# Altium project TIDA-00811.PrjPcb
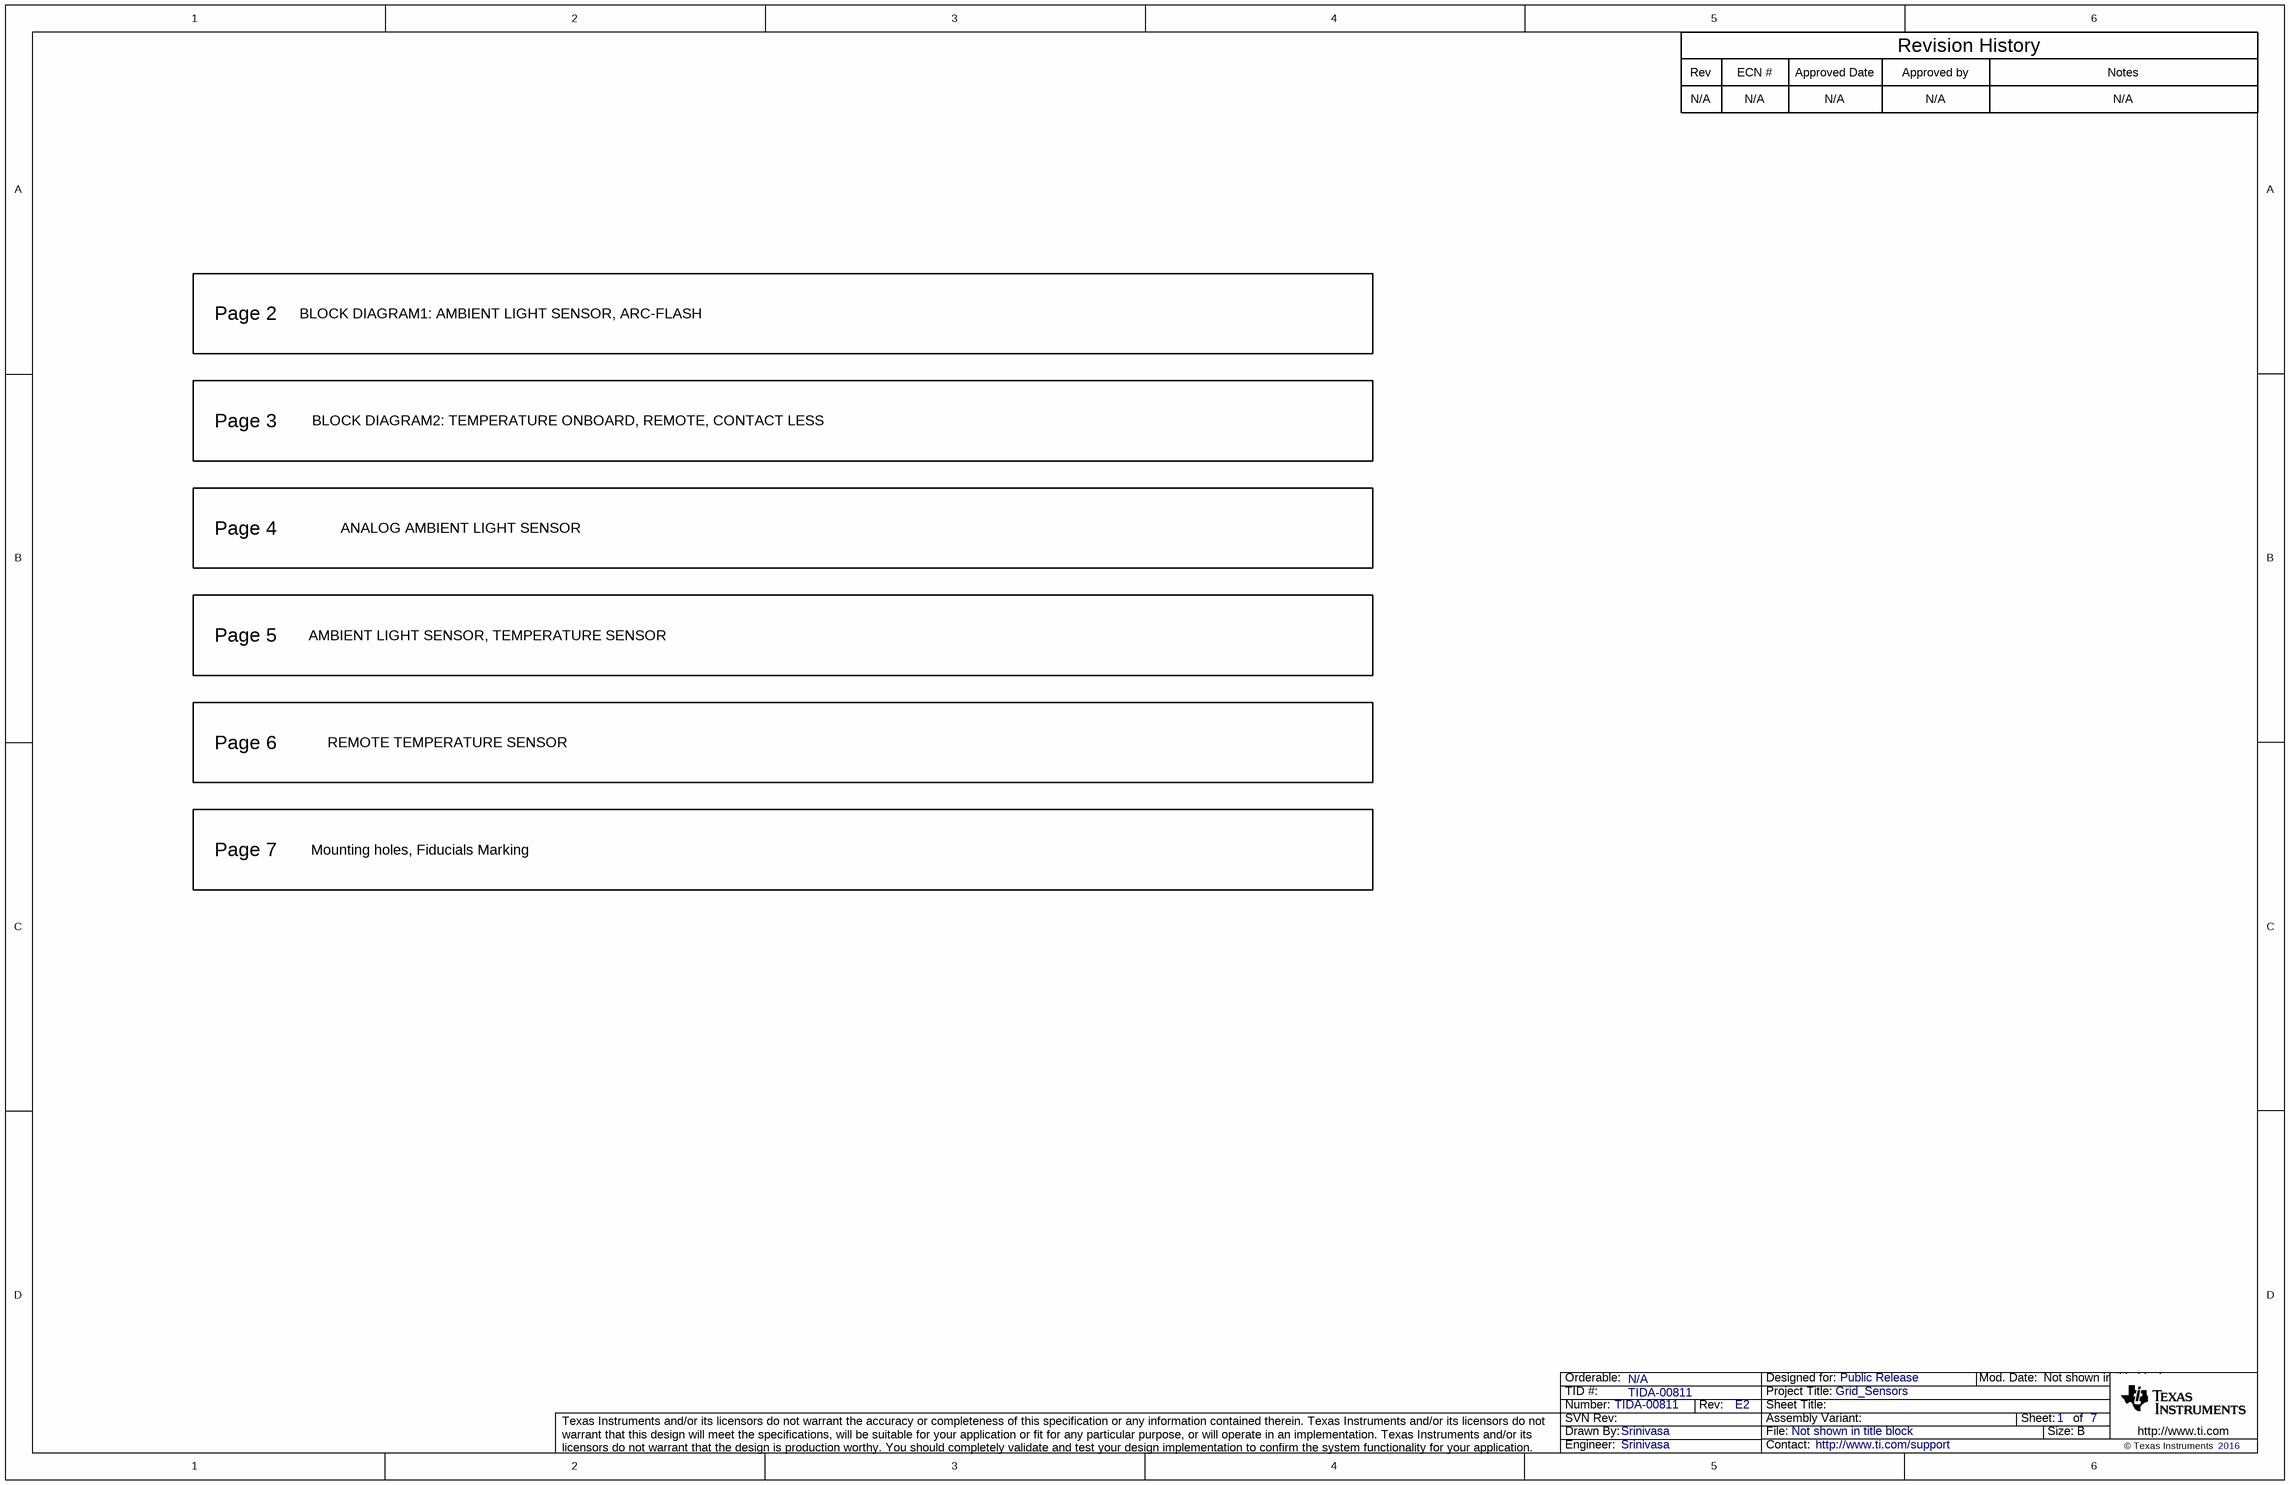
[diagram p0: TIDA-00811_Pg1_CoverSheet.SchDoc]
EVM_orderable: N/A; TID: TIDA-00811; TechSupport: http://www.ti.com/support; SCH_Rev: E2; PRJ_Title: Grid_Sensors; PRJ_Number: TIDA-00811; PRJ_Engineer: Srinivasa; PRJ_Customer: Public Release; PCB_Rev: E2; PCB_Layout: Manjunath M; CopyrightYear: 2016
7 sheets, 222 parts. Net scope: flat (ports and power ports of the same name join across sheets).
Board file: TIDA-00811_PCB.PcbDoc
Sheets:
  TIDA-00811_Pg1_CoverSheet.SchDoc
  TIDA-00811_Pg2_Block Diagram1.SchDoc
  TIDA-00811_Pg3_Block Diagram2.SchDoc
  TIDA-00811_Pg4.SchDoc
  TIDA-00811_Pg5.SchDoc
  TIDA-00811_Pg6.SchDoc
  TIDA-00811_Pg7_EVM_Hardware.SchDoc

## Sheet TIDA-00811_Pg1_CoverSheet.SchDoc
size 431 x 279 mm; Date: Not shown in title block; ApprovedBy: Not shown in title block; CheckedBy: Not shown in title block; Author: Not shown in title block; CompanyName: Not shown in title block; DrawnBy: Srinivasa; Engineer: Not shown in title block; Organization: Not shown in title block; Address1: Not shown in title block; Address2: Not shown in title block; Address3: Not shown in title block; Address4: Not shown in title block; DocumentNumber: 1; Revision: Use project parameter SCH_Rev; SheetNumber: 1; SheetTotal: 7; PageSetup: Record=PageOptions¦CenterHorizontal=True¦CenterVertical=True¦PrintScale=1.00¦XCorrection=1.00¦YCorrection=1.00¦PrintKind=0¦BorderSize=5000000¦LeftOffset=0¦BottomOffset=0¦Orientation=2¦PaperLength=1000¦PaperWidth=1000¦Scale=100¦PaperSource=15¦PrintQuality=600¦MediaType=1¦DitherType=10¦PaperKind=Letter¦PrintScaleMode=1

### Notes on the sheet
- Rev
- N/A
- ECN #
- Approved Date
- Approved by
- Revision History
- Notes
- Page 2
- BLOCK DIAGRAM1: AMBIENT LIGHT SENSOR, ARC-FLASH
- Page 3
- BLOCK DIAGRAM2: TEMPERATURE ONBOARD, REMOTE, CONTACT LESS
- Page 4
- ANALOG AMBIENT LIGHT SENSOR
- Page 5
- AMBIENT LIGHT SENSOR, TEMPERATURE SENSOR
- Page 6
- REMOTE TEMPERATURE SENSOR
- Page 7
- Mounting holes, Fiducials Marking

## Sheet TIDA-00811_Pg2_Block Diagram1.SchDoc
size 431 x 279 mm; Date: Not shown in title block; ApprovedBy: Not shown in title block; CheckedBy: Not shown in title block; Author: Not shown in title block; CompanyName: Not shown in title block; DrawnBy: Srinivasa; Engineer: Not shown in title block; Organization: Not shown in title block; Address1: Not shown in title block; Address2: Not shown in title block; Address3: Not shown in title block; Address4: Not shown in title block; DocumentNumber: 1; Revision: Use project parameter SCH_Rev; SheetNumber: 2; SheetTotal: 7; PageSetup: Record=PageOptions¦CenterHorizontal=True¦CenterVertical=True¦PrintScale=1.00¦XCorrection=1.00¦YCorrection=1.00¦PrintKind=0¦BorderSize=5000000¦LeftOffset=0¦BottomOffset=0¦Orientation=2¦PaperLength=1000¦PaperWidth=1000¦Scale=100¦PaperSource=15¦PrintQuality=600¦MediaType=1¦DitherType=10¦PaperKind=Letter¦PrintScaleMode=1

## Sheet TIDA-00811_Pg3_Block Diagram2.SchDoc
size 431 x 279 mm; Date: Not shown in title block; ApprovedBy: Not shown in title block; CheckedBy: Not shown in title block; Author: Not shown in title block; CompanyName: Not shown in title block; DrawnBy: Srinivasa; Engineer: Not shown in title block; Organization: Not shown in title block; Address1: Not shown in title block; Address2: Not shown in title block; Address3: Not shown in title block; Address4: Not shown in title block; DocumentNumber: 1; Revision: Use project parameter SCH_Rev; SheetNumber: 3; SheetTotal: 7; PageSetup: Record=PageOptions¦CenterHorizontal=True¦CenterVertical=True¦PrintScale=1.00¦XCorrection=1.00¦YCorrection=1.00¦PrintKind=0¦BorderSize=5000000¦LeftOffset=0¦BottomOffset=0¦Orientation=2¦PaperLength=1000¦PaperWidth=1000¦Scale=100¦PaperSource=15¦PrintQuality=600¦MediaType=1¦DitherType=10¦PaperKind=Letter¦PrintScaleMode=1
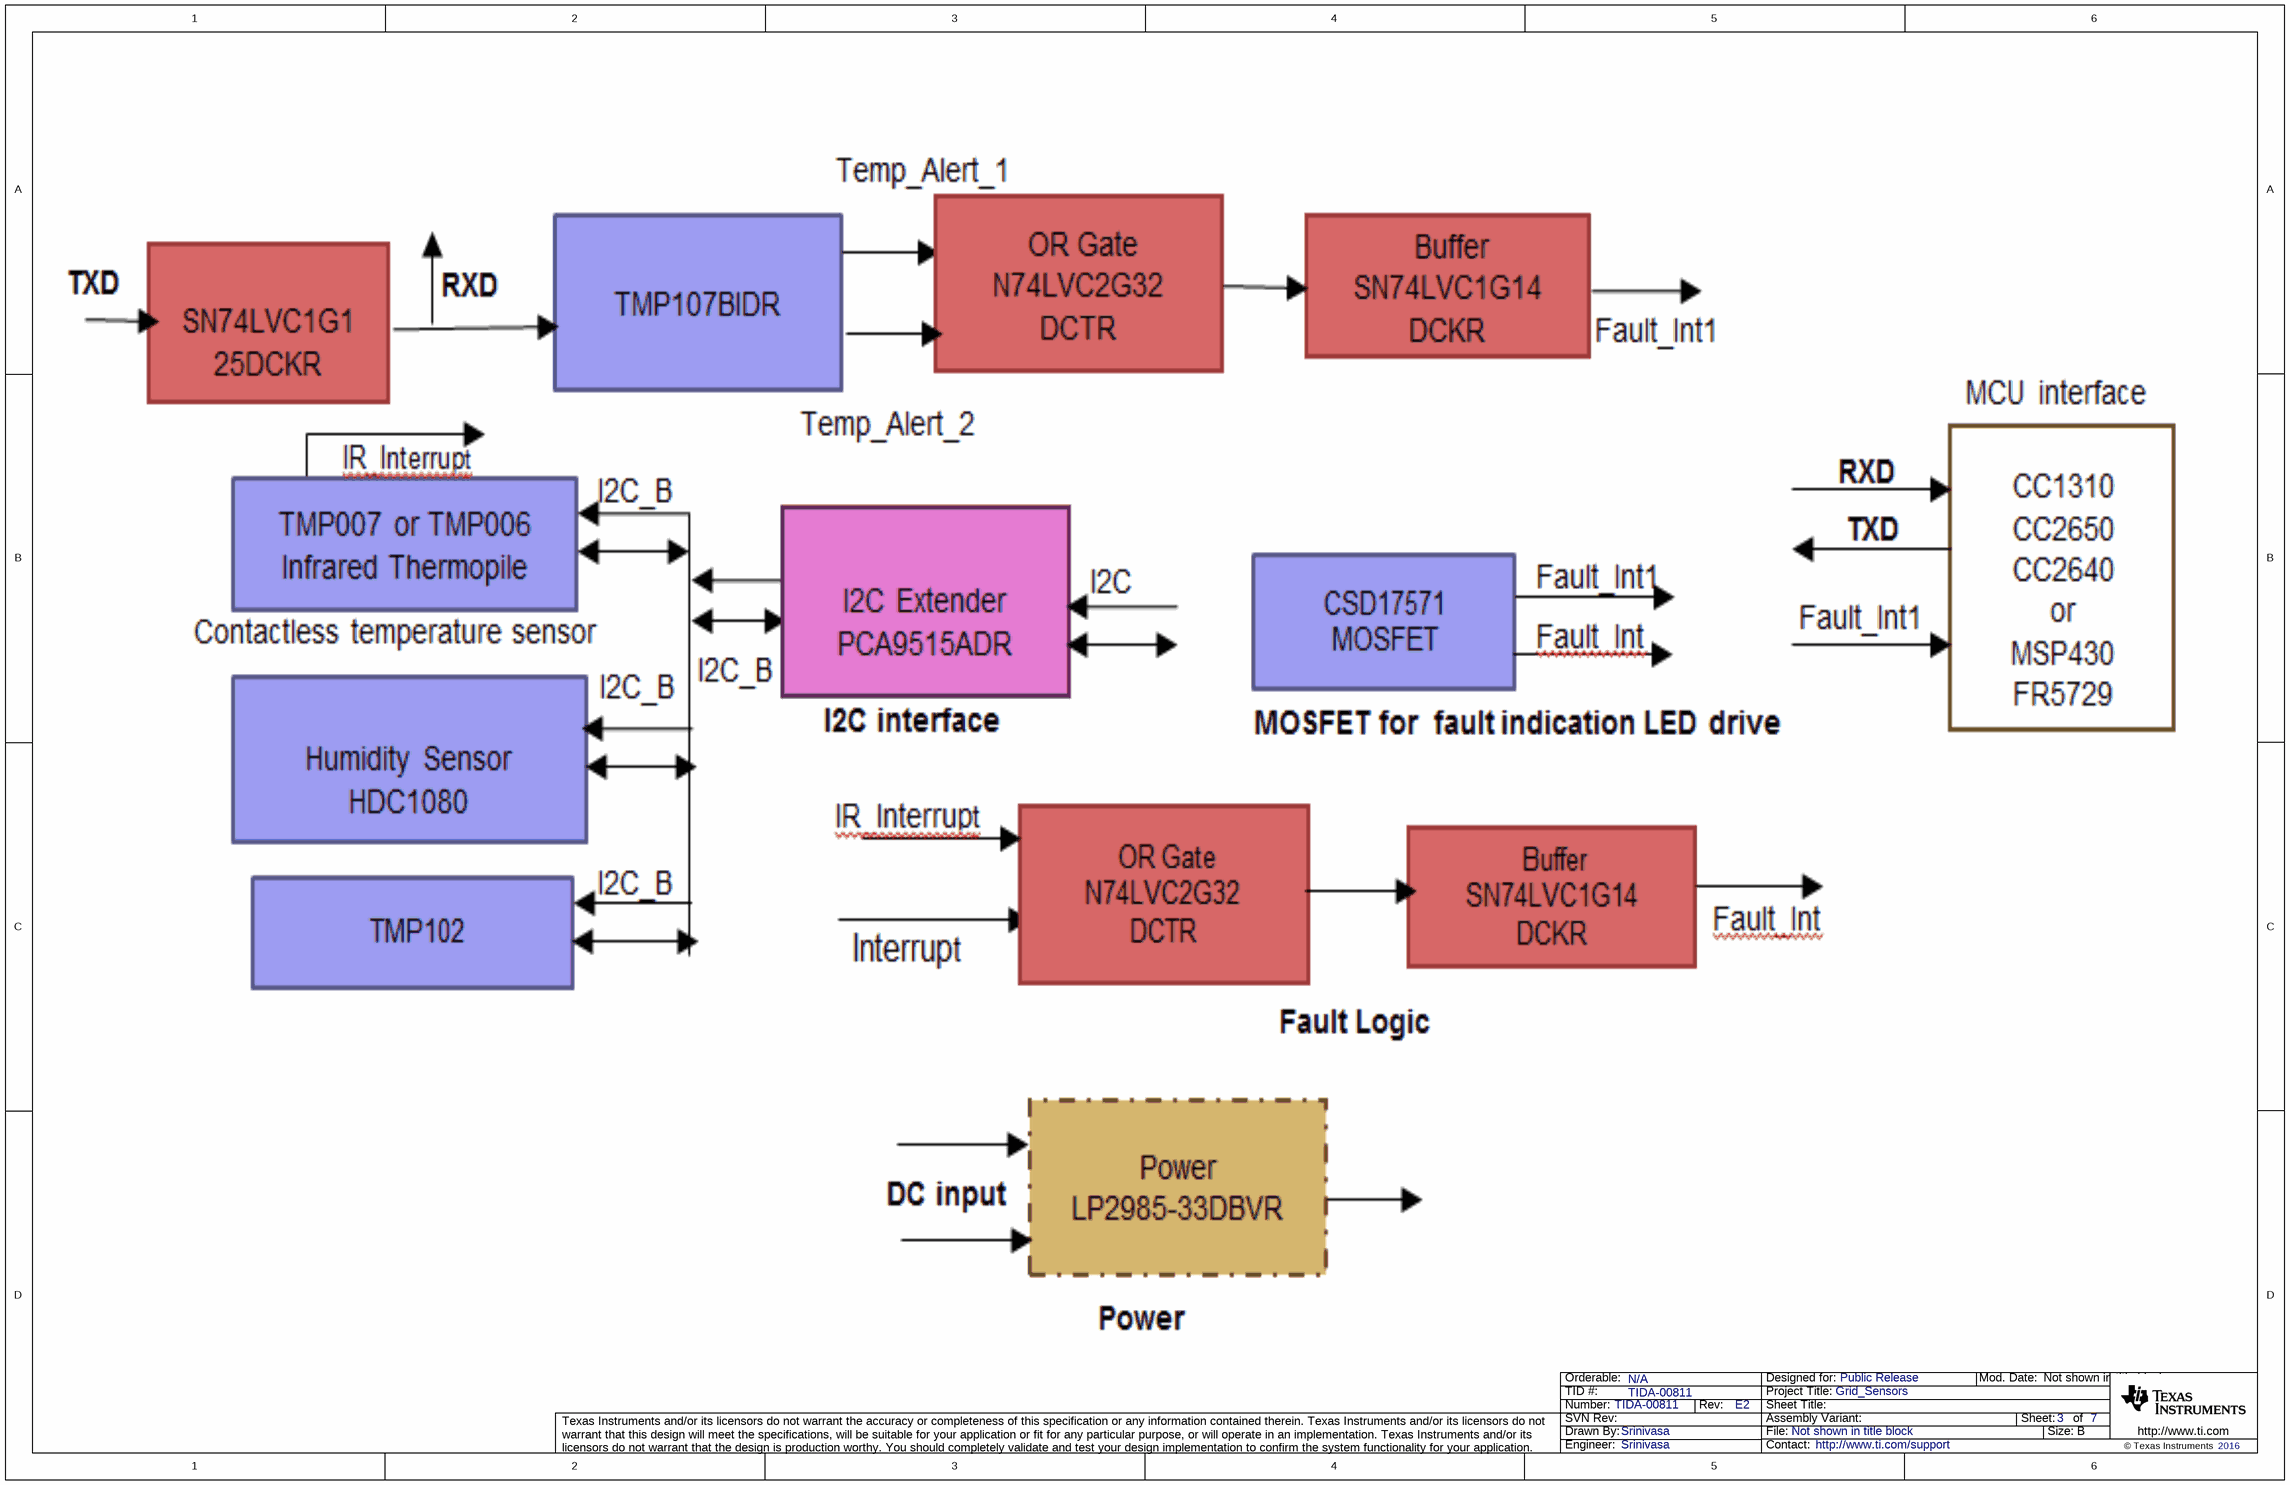
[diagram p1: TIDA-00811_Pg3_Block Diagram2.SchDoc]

## Sheet TIDA-00811_Pg4.SchDoc
size 431 x 279 mm; Date: Not shown in title block; ApprovedBy: Not shown in title block; CheckedBy: Not shown in title block; Author: Not shown in title block; CompanyName: Not shown in title block; DrawnBy: Srinivasa; Engineer: Not shown in title block; Organization: Not shown in title block; Address1: Not shown in title block; Address2: Not shown in title block; Address3: Not shown in title block; Address4: Not shown in title block; DocumentNumber: 1; Revision: Use project parameter SCH_Rev; SheetNumber: 4; SheetTotal: 7; PageSetup: Record=PageOptions¦CenterHorizontal=True¦CenterVertical=True¦PrintScale=1.00¦XCorrection=1.00¦YCorrection=1.00¦PrintKind=0¦BorderSize=5000000¦LeftOffset=0¦BottomOffset=0¦Orientation=2¦PaperLength=1000¦PaperWidth=1000¦Scale=100¦PaperSource=15¦PrintQuality=600¦MediaType=1¦DitherType=10¦PaperKind=Letter¦PrintScaleMode=1
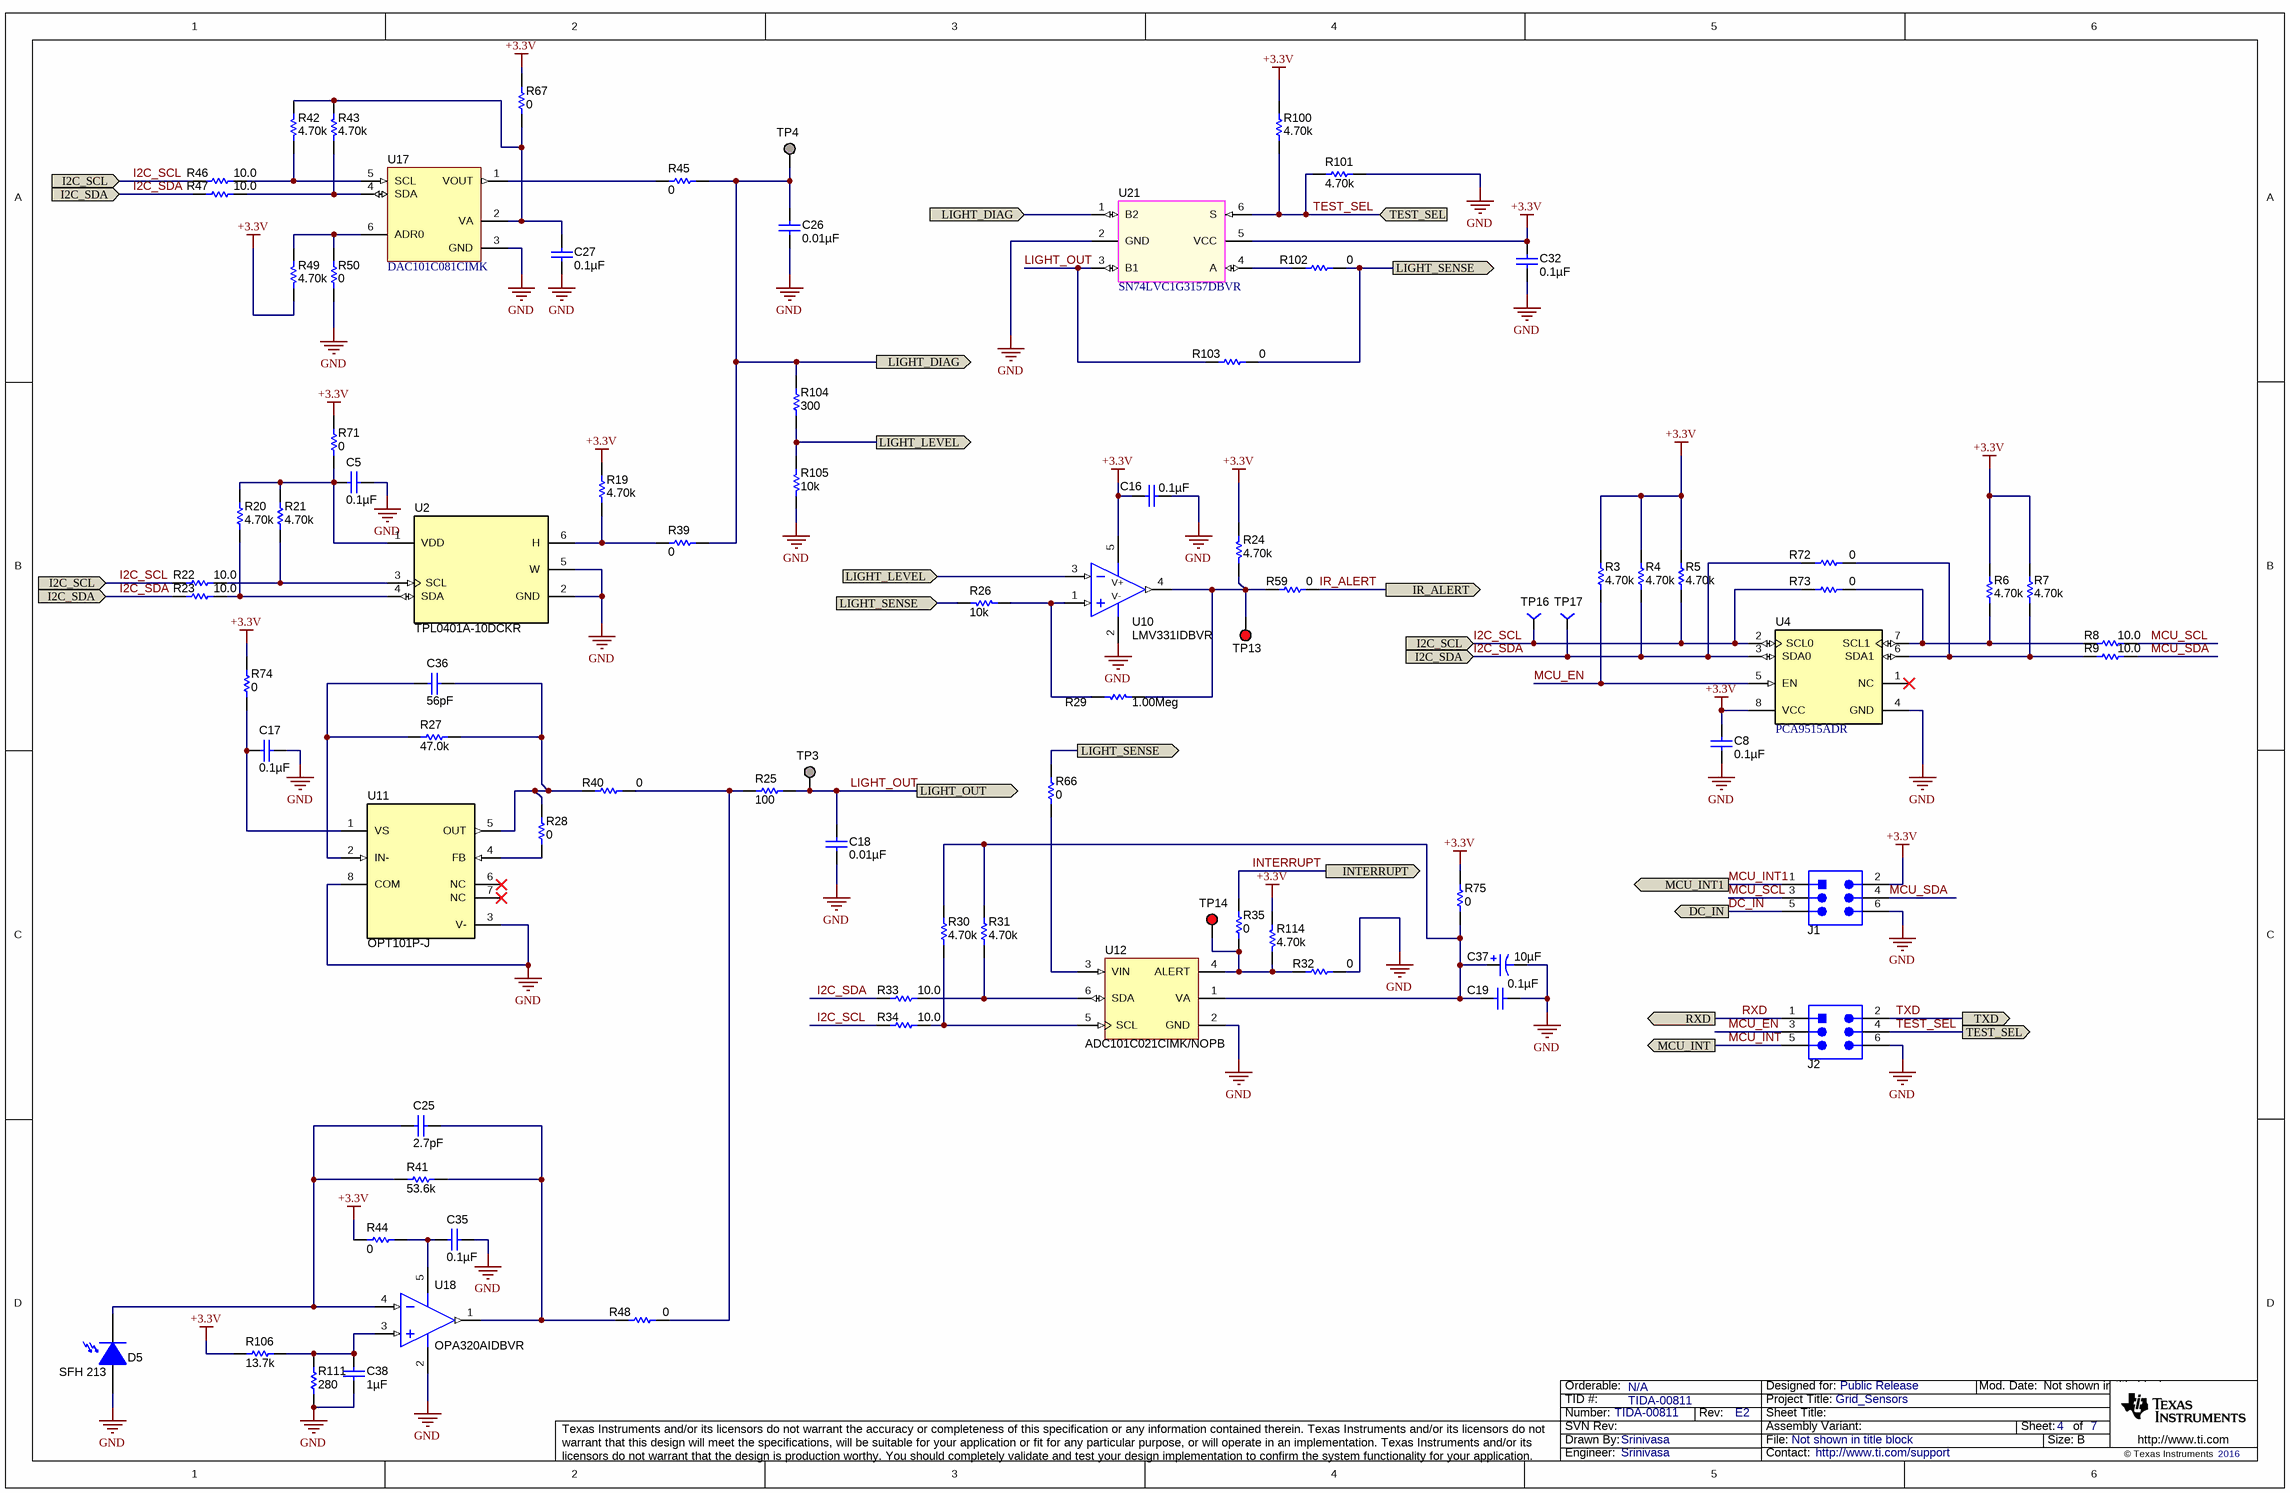
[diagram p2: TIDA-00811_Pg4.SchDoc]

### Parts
C5  ValueDisplayed: 0.1µF  [0603]  (hidden comment: 06033C104JAT2A)
C8  ValueDisplayed: 0.1µF  [0603]  (hidden comment: 06033C104JAT2A)
C16  ValueDisplayed: 0.1µF  [0603]  (hidden comment: 06033C104JAT2A)
C17  ValueDisplayed: 0.1µF  [0603]  (hidden comment: 06033C104JAT2A)
C18  ValueDisplayed: 0.01µF  [0603]  (hidden comment: C1608C0G1E103J080AA)
C19  ValueDisplayed: 0.1µF  [0603]  (hidden comment: 06033C104JAT2A)
C25  ValueDisplayed: 2.7pF  [0603]  (hidden comment: 06035A2R7CAT2A)
C26  ValueDisplayed: 0.01µF  [0603]  (hidden comment: C1608C0G1E103J080AA)
C27  ValueDisplayed: 0.1µF  [0603]
C32  ValueDisplayed: 0.1µF  [0603]
C35  ValueDisplayed: 0.1µF  [0603]  (hidden comment: 06033C104JAT2A)
C36  ValueDisplayed: 56pF  [0603]  (hidden comment: GRM1885C1H560JA01D)
C37  ValueDisplayed: 10µF  [6032-28]  (hidden comment: 293D106X9025C2TE3)
C38  ValueDisplayed: 1µF  [0603]  (hidden comment: C0603C105K4PACTU)
D5  SFH 213  [SFH_213]
J1  61300621121  [Mill-Max_802-10-006-10-001000]  (value not drawn)
J2  61300621121  [Mill-Max_802-10-006-10-001000]  (value not drawn)
R3  ValueDisplayed: 4.70k  [0603]  (hidden comment: RC0603FR-074K7L)
R4  ValueDisplayed: 4.70k  [0603]  (hidden comment: RC0603FR-074K7L)
R5  ValueDisplayed: 4.70k  [0603]  (hidden comment: RC0603FR-074K7L)
R6  ValueDisplayed: 4.70k  [0603]  (hidden comment: RC0603FR-074K7L)
R7  ValueDisplayed: 4.70k  [0603]  (hidden comment: RC0603FR-074K7L)
R8  ValueDisplayed: 10.0  [0603]  (hidden comment: CRCW060310R0FKEA)
R9  ValueDisplayed: 10.0  [0603]  (hidden comment: CRCW060310R0FKEA)
R19  ValueDisplayed: 4.70k  [0603]  (hidden comment: RC0603FR-074K7L)
R20  ValueDisplayed: 4.70k  [0603]  (hidden comment: RC0603FR-074K7L)
R21  ValueDisplayed: 4.70k  [0603]  (hidden comment: RC0603FR-074K7L)
R22  ValueDisplayed: 10.0  [0603]  (hidden comment: CRCW060310R0FKEA)
R23  ValueDisplayed: 10.0  [0603]  (hidden comment: CRCW060310R0FKEA)
R24  ValueDisplayed: 4.70k  [0603]  (hidden comment: RC0603FR-074K7L)
R25  value 100  [0603]  (hidden comment: CRCW0603100RFKEA)
R26  value 10k  [0603]  (hidden comment: CRCW060310K0FKEA)
R27  ValueDisplayed: 47.0k  [0603]  (hidden comment: RC0603FR-0747KL)
R28  ValueDisplayed: 0  [0603]  (hidden comment: RC0603JR-070RL)
R29  value 1.00Meg  [0603]  (hidden comment: CRCW06031M00FKEA)
R30  ValueDisplayed: 4.70k  [0603]  (hidden comment: RC0603FR-074K7L)
R31  ValueDisplayed: 4.70k  [0603]  (hidden comment: RC0603FR-074K7L)
R32  ValueDisplayed: 0  [0603]  (hidden comment: RC0603JR-070RL)
R33  ValueDisplayed: 10.0  [0603]  (hidden comment: CRCW060310R0FKEA)
R34  ValueDisplayed: 10.0  [0603]  (hidden comment: CRCW060310R0FKEA)
R35  ValueDisplayed: 0  [0603]  (hidden comment: RC0603JR-070RL)
R39  ValueDisplayed: 0  [0603]  (hidden comment: RC0603JR-070RL)
R40  ValueDisplayed: 0  [0603]  (hidden comment: RC0603JR-070RL)
R41  ValueDisplayed: 53.6k  [0603]  (hidden comment: RG1608P-5362-B-T5)
R42  ValueDisplayed: 4.70k  [0603]  (hidden comment: RC0603FR-074K7L)
R43  ValueDisplayed: 4.70k  [0603]  (hidden comment: RC0603FR-074K7L)
R44  ValueDisplayed: 0  [0603]  (hidden comment: RC0603JR-070RL)
R45  ValueDisplayed: 0  [0603]  (hidden comment: RC0603JR-070RL)
R46  ValueDisplayed: 10.0  [0603]  (hidden comment: CRCW060310R0FKEA)
R47  ValueDisplayed: 10.0  [0603]  (hidden comment: CRCW060310R0FKEA)
R48  ValueDisplayed: 0  [0603]  (hidden comment: RC0603JR-070RL)
R49  ValueDisplayed: 4.70k  [0603]  (hidden comment: RC0603FR-074K7L)
R50  ValueDisplayed: 0  [0603]  (hidden comment: RC0603JR-070RL)
R59  ValueDisplayed: 0  [0603]  (hidden comment: RC0603JR-070RL)
R66  ValueDisplayed: 0  [0603]  (hidden comment: RC0603JR-070RL)
R67  ValueDisplayed: 0  [0603]  (hidden comment: RC0603JR-070RL)
R71  ValueDisplayed: 0  [0603]  (hidden comment: RC0603JR-070RL)
R72  ValueDisplayed: 0  [0603]  (hidden comment: RC0603JR-070RL)
R73  ValueDisplayed: 0  [0603]  (hidden comment: RC0603JR-070RL)
R74  ValueDisplayed: 0  [0603]  (hidden comment: RC0603JR-070RL)
R75  ValueDisplayed: 0  [0603]  (hidden comment: RC0603JR-070RL)
R100  ValueDisplayed: 4.70k  [0603]  (hidden comment: RC0603FR-074K7L)
R101  ValueDisplayed: 4.70k  [0603]  (hidden comment: RC0603FR-074K7L)
R102  ValueDisplayed: 0  [0603]  (hidden comment: ERJ-3GEY0R00V)
R103  ValueDisplayed: 0  [0603]  (hidden comment: ERJ-3GEY0R00V)
R104  value 300  [0603]  (hidden comment: CRCW0603300RJNEA)
R105  value 10k  [0603]  (hidden comment: CRCW060310K0FKEA)
R106  ValueDisplayed: 13.7k  [0603]  (hidden comment: CRCW060313K7FKEA)
R111  ValueDisplayed: 280  [0603]  (hidden comment: RC0603FR-07280RL)
R114  ValueDisplayed: 4.70k  [0603]  (hidden comment: RC0603FR-074K7L)
TP3  TESTPOINT  [TP_H045P075]  (value not drawn)  (no BOM)
TP4  TESTPOINT  [TP_H045P075]  (value not drawn)  (no BOM)
TP13  5000  [Keystone5000]  (value not drawn)
TP14  5000  [Keystone5000]  (value not drawn)
TP16  TP-5001-BLACK  [TH-40]  (value not drawn)
TP17  TP-5001-BLACK  [TH-40]  (value not drawn)
U2  TPL0401A-10DCKR  [DCK0006A_N]
U4  PCA9515ADR  [D0008A_N]
U10  LMV331IDBVR  [DBV0005A_N]
U11  OPT101P-J  [DTL0008A_N]
U12  ADC101C021CIMK/NOPB  [MK06A_N]
U17  DAC101C081CIMK  [MK06A_N]
U18  OPA320AIDBVR  [DBV0005A_N]
U21  SN74LVC1G3157DBVR  [SOT23-6]

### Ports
DC_IN (out), I2C_SCL (in), I2C_SDA (in), INTERRUPT (out), IR_ALERT (out), LIGHT_DIAG (in), LIGHT_DIAG (out), LIGHT_LEVEL (in), LIGHT_LEVEL (out), LIGHT_OUT (out), LIGHT_SENSE (in), LIGHT_SENSE (out), MCU_INT1 (out), MCU_INT (out), RXD (out), TEST_SEL (in), TEST_SEL (out), TXD (out)

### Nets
+3.3V: C8.1 C16.2 C32.1 J1.2 R3.2 R4.2 R5.2 R6.2 R7.2 R19.1 R24.2 R44.2 R49.1 R67.2 R71.2 R74.2 R75.2 R100.1 R106.1 R114.2 U4.8(VCC) U10.5(V+) U21.5(VCC)
GND: C5.1 C8.2 C16.1 C17.1 C18.1 C19.1 C26.1 C27.2 C32.2 C35.1 C37.2(-) C38.2 D5.1(A) J1.6 J2.6 R32.2 R50.1 R101.1 R105.2 R111.1 U2.2(GND) U2.5(W) U4.4(GND) U10.2(V-) U11.3(V-) U11.8(COM) U12.2(GND) U17.3(GND) U18.2(V-) U21.2(GND)
DC_IN: J1.5 ; port DC_IN
I2C_SCL: R5.1 R22.2 R34.2 R46.1 R73.2 TP16.1 U4.2(SCL0) ; port I2C_SCL
I2C_SDA: R4.1 R23.2 R33.2 R47.1 R72.2 TP17.1 U4.3(SDA0) ; port I2C_SDA
INTERRUPT: R35.2 ; port INTERRUPT
IR_ALERT: R59.2 ; port IR_ALERT
LIGHT_DIAG: C26.2 R39.2 R45.2 R104.2 TP4.1 U21.1(B2) ; port LIGHT_DIAG
LIGHT_LEVEL: R104.1 R105.1 U10.3(IN-) ; port LIGHT_LEVEL
LIGHT_OUT: C18.2 R25.2 R103.1 TP3.1 U21.3(B1) ; port LIGHT_OUT
LIGHT_SENSE: R26.1 R66.2 R102.1 R103.2 ; port LIGHT_SENSE
MCU_EN: J2.3 R3.1 U4.5(EN)
MCU_INT: J2.5 ; port MCU_INT
MCU_INT1: J1.1 ; port MCU_INT1
MCU_SCL: J1.3 R8.2
MCU_SDA: J1.4 R9.2
RXD: J2.1 ; port RXD
TEST_SEL: J2.4 R100.2 R101.2 U21.6(S) ; port TEST_SEL
TXD: J2.2 ; port TXD
NetC5_2: C5.2 R20.2 R21.2 R71.1 U2.1(VDD)
NetC17_2: C17.2 R74.1 U11.1(VS)
NetC19_2: C19.2 C37.1(+) R30.2 R31.2 R75.1 U12.1(VA)
NetC25_1: C25.1 R41.2 R48.1 U18.1(OUT)
NetC25_2: C25.2 D5.2(C) R41.1 U18.4(IN-)
NetC27_1: C27.1 R42.2 R43.2 R67.1 U17.2(VA)
NetC35_2: C35.2 R44.1 U18.5(V+)
NetC36_1: C36.1 R27.2 R28.1 R40.1 U11.5(OUT)
NetC36_2: C36.2 R27.1 U11.2(IN-)
NetC38_1: C38.1 R106.2 R111.2 U18.3(IN+)
NetR6_1: R6.1 R8.1 R73.1 U4.7(SCL1)
NetR7_1: R7.1 R9.1 R72.1 U4.6(SDA1)
NetR19_2: R19.2 R39.1 U2.6(H)
NetR20_1: R20.1 R23.1 U2.4(SDA)
NetR21_1: R21.1 R22.1 U2.3(SCL)
NetR24_1: R24.1 R29.2 R59.1 TP13.1 U10.4(OUT)
NetR25_1: R25.1 R40.2 R48.2
NetR26_2: R26.2 R29.1 U10.1(IN+)
NetR28_2: R28.2 U11.4(FB)
NetR30_1: R30.1 R34.1 U12.5(SCL)
NetR31_1: R31.1 R33.1 U12.6(SDA)
NetR32_1: R32.1 R35.1 R114.1 TP14.1 U12.4(ALERT)
NetR42_1: R42.1 R46.2 U17.5(SCL)
NetR43_1: R43.1 R47.2 U17.4(SDA)
NetR45_1: R45.1 U17.1(VOUT)
NetR49_2: R49.2 R50.2 U17.6(ADR0)
NetR66_1: R66.1 U12.3(VIN)
NetR102_2: R102.2 U21.4(A)

Not connected (* = marked no-connect by the designer): U4 1(NC)*; U11 6(NC)* 7(NC)*

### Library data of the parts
C5 C8 C17 C19 C35 = 06033C104JAT2A: CAP, CERM, 0.1 µF, 25 V, +/- 5%, X7R, 0603; Manufacturer: AVX; Polarized: N; CompType: Capacitor; Value: 0.1uF; U/M: EA; Cap_F: 0.0000001; Tolerance_%: 5; ESR_ohm: 0.05; Value1: 0.05 ohm; VDC_V: 25; Value2: 25V; TaMin_C: -55; TaMax_C: 125; AEC Category: Q200
C16 C27 C32 = 06033C104JAT2A: CAP, CERM, 0.1uF, 25V, +/-5%, X7R, 0603; Manufacturer: AVX; Polarized: N; CompType: Capacitor; U/M: EA; Cap_F: 0.0000001; Tolerance_%: 5; ESR_Ohm: 0.05; Value1: 0.05 ohm; VDC_V: 25; TaMin_C: -55; TaMax_C: 125
C18 C26 = C1608C0G1E103J: CAP, CERM, 0.01uF, 25V, +/-5%, C0G/NP0, 0603; Manufacturer: TDK; Polarized: N; CompType: Capacitor; U/M: EA; Cap_F: 0.00000001; Tolerance_%: 5; Value1: Unknown; VDC_V: 25; TaMin_C: -55; TaMax_C: 125
C25 = 06035A2R7CAT2A: CAP, CERM, 2.7 pF, 50 V,+/- 9%, C0G/NP0, 0603; Manufacturer: AVX; Polarized: N; CompType: Capacitor; Value: 2.7pF; U/M: EA; Cap_F: 0.0000000000027; Tolerance_%: 9; ESR_ohm: 0.902; Value1: 0.902 ohm; VDC_V: 50; Value2: 50V; TaMin_C: -55; TaMax_C: 125; SizeArea_mm2: 1.28; SizeAreaWB_mm2: 4.68; SizeX_mm: 1.6; SizeY_mm: 0.8; SizeZ_mm: 1; AEC Category: Q200; Green_Lifecycle: Not Set; Green_REACh: Incomplete
C36 = GRM1885C1H560JA01D: CAP, CERM, 56 pF, 50 V, +/- 5%, C0G/NP0, 0603; Manufacturer: MuRata; Polarized: N; CompType: Capacitor; Value: 56pF; U/M: EA; Cap_F: 0.000000000056; Tolerance_%: 5; Value1: Unknown; VDC_V: 50; Value2: 50V; TaMin_C: -55; TaMax_C: 125; SizeArea_mm2: 1.28; SizeAreaWB_mm2: 4.68; SizeX_mm: 1.6; SizeY_mm: 0.8; SizeZ_mm: 1; AEC Category: Q200
C37 = 293D106X9025C2TE3: CAP, TA, 10 µF, 25 V, +/- 10%, 1.5 ohm, SMD; Manufacturer: Vishay-Sprague; Polarized: Y; CompType: Capacitor; Value: 10uF; U/M: EA; Cap_F: 0.00001; Tolerance_%: 10; Value1: 1.5 ohm; VDC_V: 25; Value2: 25V; ESR_ohm: 1.5; IRMS_A: 0.27; TaMin_C: -55; TaMax_C: 125; Cap_Case: C; AEC Category: Q200
C38 = C0603C105K4PACTU: CAP, CERM, 1 µF, 16 V,+/- 10%, X5R, 0603; Manufacturer: Kemet; Polarized: N; CompType: Capacitor; Value: 1uF; U/M: EA; Cap_F: 0.000001; Tolerance_%: 10; Value1: Unknown; VDC_V: 16; Value2: 16V; TaMin_C: -55; TaMax_C: 85; SizeArea_mm2: 1.28; SizeAreaWB_mm2: 4.68; SizeX_mm: 1.6; SizeY_mm: 0.8; SizeZ_mm: 1; AEC Category: Q200; Green_Lifecycle: Active; Green_REACh: Passed
D5 = SFH 213: Silicon PIN Photodiode, TH; Manufacturer: OSRAM; SymbolCreator: Altium
J1 J2 = 802-10-006-10-001000: Header, 2.54 mm, 3x2, Gold, TH; Manufacturer: Mill-Max; SymbolCreator: a0412235; Pitch_mm: 2.54; Gender: Male; Shrouded: N; Row_Count: 2
R3-R7 R19-R21 R24 R30 R31 R42 R43 R49 R100 R101 R114 = RC0603FR-074K7L: RES, 4.70 k, 1%, 0.1 W, 0603; Manufacturer: Yageo America; CompType: Resistor; Value: 4.70k; Res_ohm: 4700; Value_Code: 4k70; Tolerance_%: 1; Power_W: 0.1; Value2: 0.1W; VDC_V: 150; TempCo: 200 ppm/C; U/M: EA; AEC Category: Q200
R8 R9 R22 R23 R33 R34 R46 R47 = CRCW060310R0FKEA: RES, 10.0, 1%, 0.1 W, 0603; Manufacturer: Vishay-Dale; CompType: Resistor; Value: 10.0; Res_ohm: 10; Value_Code: 10R0; Tolerance_%: 1; Power_W: 0.1; Value2: 0.1W; VDC_V: 75; TempCo: 100 ppm/C; SizeArea_mm2: 1.28; SizeX_mm: 1.6; SizeY_mm: 0.8; EIA_Code: E96; U/M: EA; AEC Category: Q200
R25 = CRCW0603100RFKEA: RES, 100 ohm, 1%, 0.1W, 0603; Manufacturer: Vishay-Dale; CompType: Resistor; Value_Code: 100R; Tolerance_%: 1; Power_W: 0.1; VDC_V: 75; TempCo: 100 ppm/C; EIA_Code: E96; U/M: EA
R26 R105 = RNCF0603TKY10K0: RES, 10.0k ohm, 1%, 0.1W, 0603; Manufacturer: Stackpole Electronics Inc; CompType: Resistor; Res_ohm: 10000; Value_Code: 10k0; Tolerance_%: 0.01; Value1: 0.01%; Power_W: 0.063; Value2: 0.063W; VDC_V: 50; TempCo: 5 ppm/C; U/M: EA
R27 = RC0603FR-0747KL: RES, 47.0 k, 1%, 0.1 W, 0603; Manufacturer: Yageo America; CompType: Resistor; Value: 47.0k; Res_ohm: 47000; Value_Code: 47k0; Tolerance_%: 1; Power_W: 0.1; Value2: 0.1W; VDC_V: 150; TempCo: 200 ppm/C; U/M: EA; AEC Category: Q200
R28 R32 R35 R39 R40 R44 R45 R50 R59 R66 R67 R71 R74 R75 = RC0603JR-070RL: RES, 0, 5%, 0.1 W, 0603; Manufacturer: Yageo America; CompType: Resistor; Value: 0; Value_Code: 0000; Tolerance_%: 5; Power_W: 0.1; Value2: 0.1W; VDC_V: 50; TempCo: 200 ppm/C; EIA_Code: E24; U/M: EA; AEC Category: Q200
R29 = CRCW06031M00FKEA: RES, 1.00Meg ohm, 1%, 0.1W, 0603; Manufacturer: Vishay-Dale; CompType: Resistor; Res_ohm: 1000000; Value_Code: 1M00; Tolerance_%: 1; Power_W: 0.1; VDC_V: 75; TempCo: 100 ppm/C; EIA_Code: E96; U/M: EA
R41 = RG1608P-5362-B-T5: RES, 53.6 k, 0.1%, 0.1 W, 0603; Manufacturer: Susumu Co Ltd; CompType: Resistor; Value: 53.6k; Res_ohm: 53600; Value_Code: 53k6; Tolerance_%: 0.1; Value2: 0.1W; VDC_V: 75; TempCo: 25 ppm/C; SizeArea_mm2: 1.28; SizeX_mm: 1.6; SizeY_mm: 0.8; SizeZ_mm: 1; EIA_Code: E192; U/M: EA; AEC Category: Q200
R48 = RC0603JR-070RL: RES, 0, 5%, 0.1 W, 0603; Manufacturer: Yageo America; CompType: Resistor; Value: 0; Value_Code: 0000; Tolerance_%: 5; Power_W: 0.1; Value2: 0.1W; VDC_V: 50; TempCo: 200 ppm/C; EIA_Code: E24; U/M: EA
R72 R73 = RC0603JR-070RL: RES, 0, 5%, 0.1 W, 0603; Manufacturer: Yageo America; CompType: Resistor; Value: 0; Value_Code: 0000; Tolerance_%: 5; Power_W: 0.1; Value2: 0.1W; VDC_V: 50; TempCo: 200 ppm/C; SizeArea_mm2: 1.28; SizeX_mm: 1.6; SizeY_mm: 0.8; SizeZ_mm: 1; EIA_Code: E24; U/M: EA; AEC Category: Q200
R102 R103 = ERJ-3GEY0R00V: RES, 0, 5%, 0.1 W, 0603; Manufacturer: Panasonic; CompType: Resistor; Value: 0; Value_Code: 0000; Tolerance_%: 5; Power_W: 0.1; Value2: 0.1W; VDC_V: 50; TempCo: 600 ppm/C; EIA_Code: E24; U/M: EA; AEC Category: Q200
R104 = CRCW0603300RJNEA: RES, 300 ohm, 5%, 0.1W, 0603; Manufacturer: Vishay-Dale; CompType: Resistor; Value_Code: 300R; Tolerance_%: 5; Power_W: 0.1; VDC_V: 75; TempCo: 200 ppm/C; EIA_Code: E24; U/M: EA
R106 = CRCW060313K7FKEA: RES, 13.7 k, 1%, 0.1 W, 0603; Manufacturer: Vishay-Dale; CompType: Resistor; Value: 13.7k; Res_ohm: 13700; Value_Code: 13k7; Tolerance_%: 1; Power_W: 0.1; Value2: 0.1W; VDC_V: 75; TempCo: 100 ppm/C; SizeArea_mm2: 1.28; SizeX_mm: 1.6; SizeY_mm: 0.8; EIA_Code: E96; U/M: EA; AEC Category: Q200; Green_Lifecycle: Active; Green_REACh: Passed
R111 = RC0603FR-07280RL: RES, 280, 1%, 0.1 W, 0603; Manufacturer: Yageo America; CompType: Resistor; Value: 280; Value_Code: 280R; Tolerance_%: 1; Power_W: 0.1; Value2: 0.1W; VDC_V: 150; TempCo: 200 ppm/C; SizeArea_mm2: 1.28; SizeX_mm: 1.6; SizeY_mm: 0.8; EIA_Code: E96; U/M: EA; AEC Category: Q200
TP3 TP4 = TP_H0.45P0.75: Manufacturer: Texas Instruments; CompType: Pad
TP13 TP14 = 5000: Test Point, Miniature, Red, TH; Manufacturer: Keystone; CompType: Test Point Loop; U/M: EA
TP16 TP17 = TP-5001-BLACK: Test Point,  Black, Thru Hole Color Keyed; Manufacturer: Keystone; PartNumber: 5001; area: 10.000; Value: 5001
U2 = TPL0401A-10DCKR: 128 TAPS Single Channel Digital Potentiometer with I2C Interface, DCK0006A; Manufacturer: Texas Instruments; SymbolCreator: Altium; CompType: IC; U/M: EA
U4 = PCA9515ADR: Dual Bidirectional I2C Bus and SMBus Repeater, 2 Channel Width, 2.3 to 3.6 V, -40 to 85 degC, 8-pin SOIC (D), Green (RoHS & no Sb/Br); Manufacturer: Texas Instruments; Alternate PartNumber: Equivalent; SubFamily: I2C Hub, Buffer, Repeater; No. of Outputs: 2; VCC(Max)(V): 3.6; VCC(Min)(V): 2.3; Max Frequency(kHz): 400; Vcc range(V): 2.3 to 5.5; 5V Tolerant I/O: Yes
U10 = LMV331IDBV: Single General Purpose Low-Voltage Comparator, DBV0005A; Manufacturer: Texas Instruments; SymbolCreator: a0411595; CompType: OpAmp IC
U11 = OPT101P-J: Monolithic Photodiode and Single-Supply Transimpedance Amplifier, DTL0008A; Manufacturer: Texas Instruments; SymbolCreator: Altium; CompType: IC; U/M: EA
U12 = ADC101C021CIMK/NOPB: I2C-Compatible, 10-Bit Analog-to-Digital Converter (ADC) with Alert Pin, 6-pin Tiny SOT23, Pb-Free; Manufacturer: Texas Instruments; PackageTopMarking: X33C*XTT; PowerWise: N; CompType: ADC IC
U17 = DAC101C081CIMK: 10-Bit Micro Power Digital-to-Analog Converter with an I2C-Compatible Interface, 6-pin Tiny SOT23; PartNumber: DAC101C081CIMK/NOPB; Manufacturer: Texas Instruments; PackageTopMarking: X85C*XTT; PowerWise: N; CompType: D/A Converter
U18 = OPA320AIDBVR: Precision, 20 MHz, 0.9 pA Ib, RRIO, CMOS Operational Amplifier, 1.8 to 5.5 V, -40 to 125 degC, 5-pin SOT23 (DBV0005A), Green (RoHS & no Sb/Br); Manufacturer: Texas Instruments; Alternate PartNumber: Equivalent; CMRR(Min)(dB): 100; IIB(Max)(pA): 0.9; Iq per channel(Max)(mA): 1.75; Number of Channels: 2; Offset Drift(Typ)(uV/C): 1.5; Slew Rate(Typ)(V/us): 10; Sub Family: High Output Current Amplifier (>=50mA), Low Input Bias Current Amp (<=10pA), Low Noise Amp (<=10nV/rtHz), Low Offset Voltage Amplifier (<=500uV), Low Supply Voltage Amplifier (<=2.7V), Precision Amplifier; Total Supply Voltage(Max)(+5V is 5, +/-5V is 10): 5.5; Total Supply Voltage(Min)(+5V is 5, +/-5V is 10): 1.8; Vio (25C)(Max)(mV): 0.15; Vn at 1kHz(Typ)(nV/rtHz): 8.5
U21 = SN74LVC1G3157DBVR: IC, SWITCH, SPDT, SOT23-6; Manufacturer: TEXAS INSTRUMENTS; SymbolCreator: x0199378

## Sheet TIDA-00811_Pg5.SchDoc
size 431 x 279 mm; Date: Not shown in title block; ApprovedBy: Not shown in title block; CheckedBy: Not shown in title block; Author: Not shown in title block; CompanyName: Not shown in title block; DrawnBy: Srinivasa; Engineer: Not shown in title block; Organization: Not shown in title block; Address1: Not shown in title block; Address2: Not shown in title block; Address3: Not shown in title block; Address4: Not shown in title block; DocumentNumber: 1; Revision: Use project parameter SCH_Rev; SheetNumber: 5; SheetTotal: 7; PageSetup: Record=PageOptions¦CenterHorizontal=True¦CenterVertical=True¦PrintScale=1.00¦XCorrection=1.00¦YCorrection=1.00¦PrintKind=0¦BorderSize=5000000¦LeftOffset=0¦BottomOffset=0¦Orientation=2¦PaperLength=1000¦PaperWidth=1000¦Scale=100¦PaperSource=15¦PrintQuality=600¦MediaType=1¦DitherType=10¦PaperKind=Letter¦PrintScaleMode=1
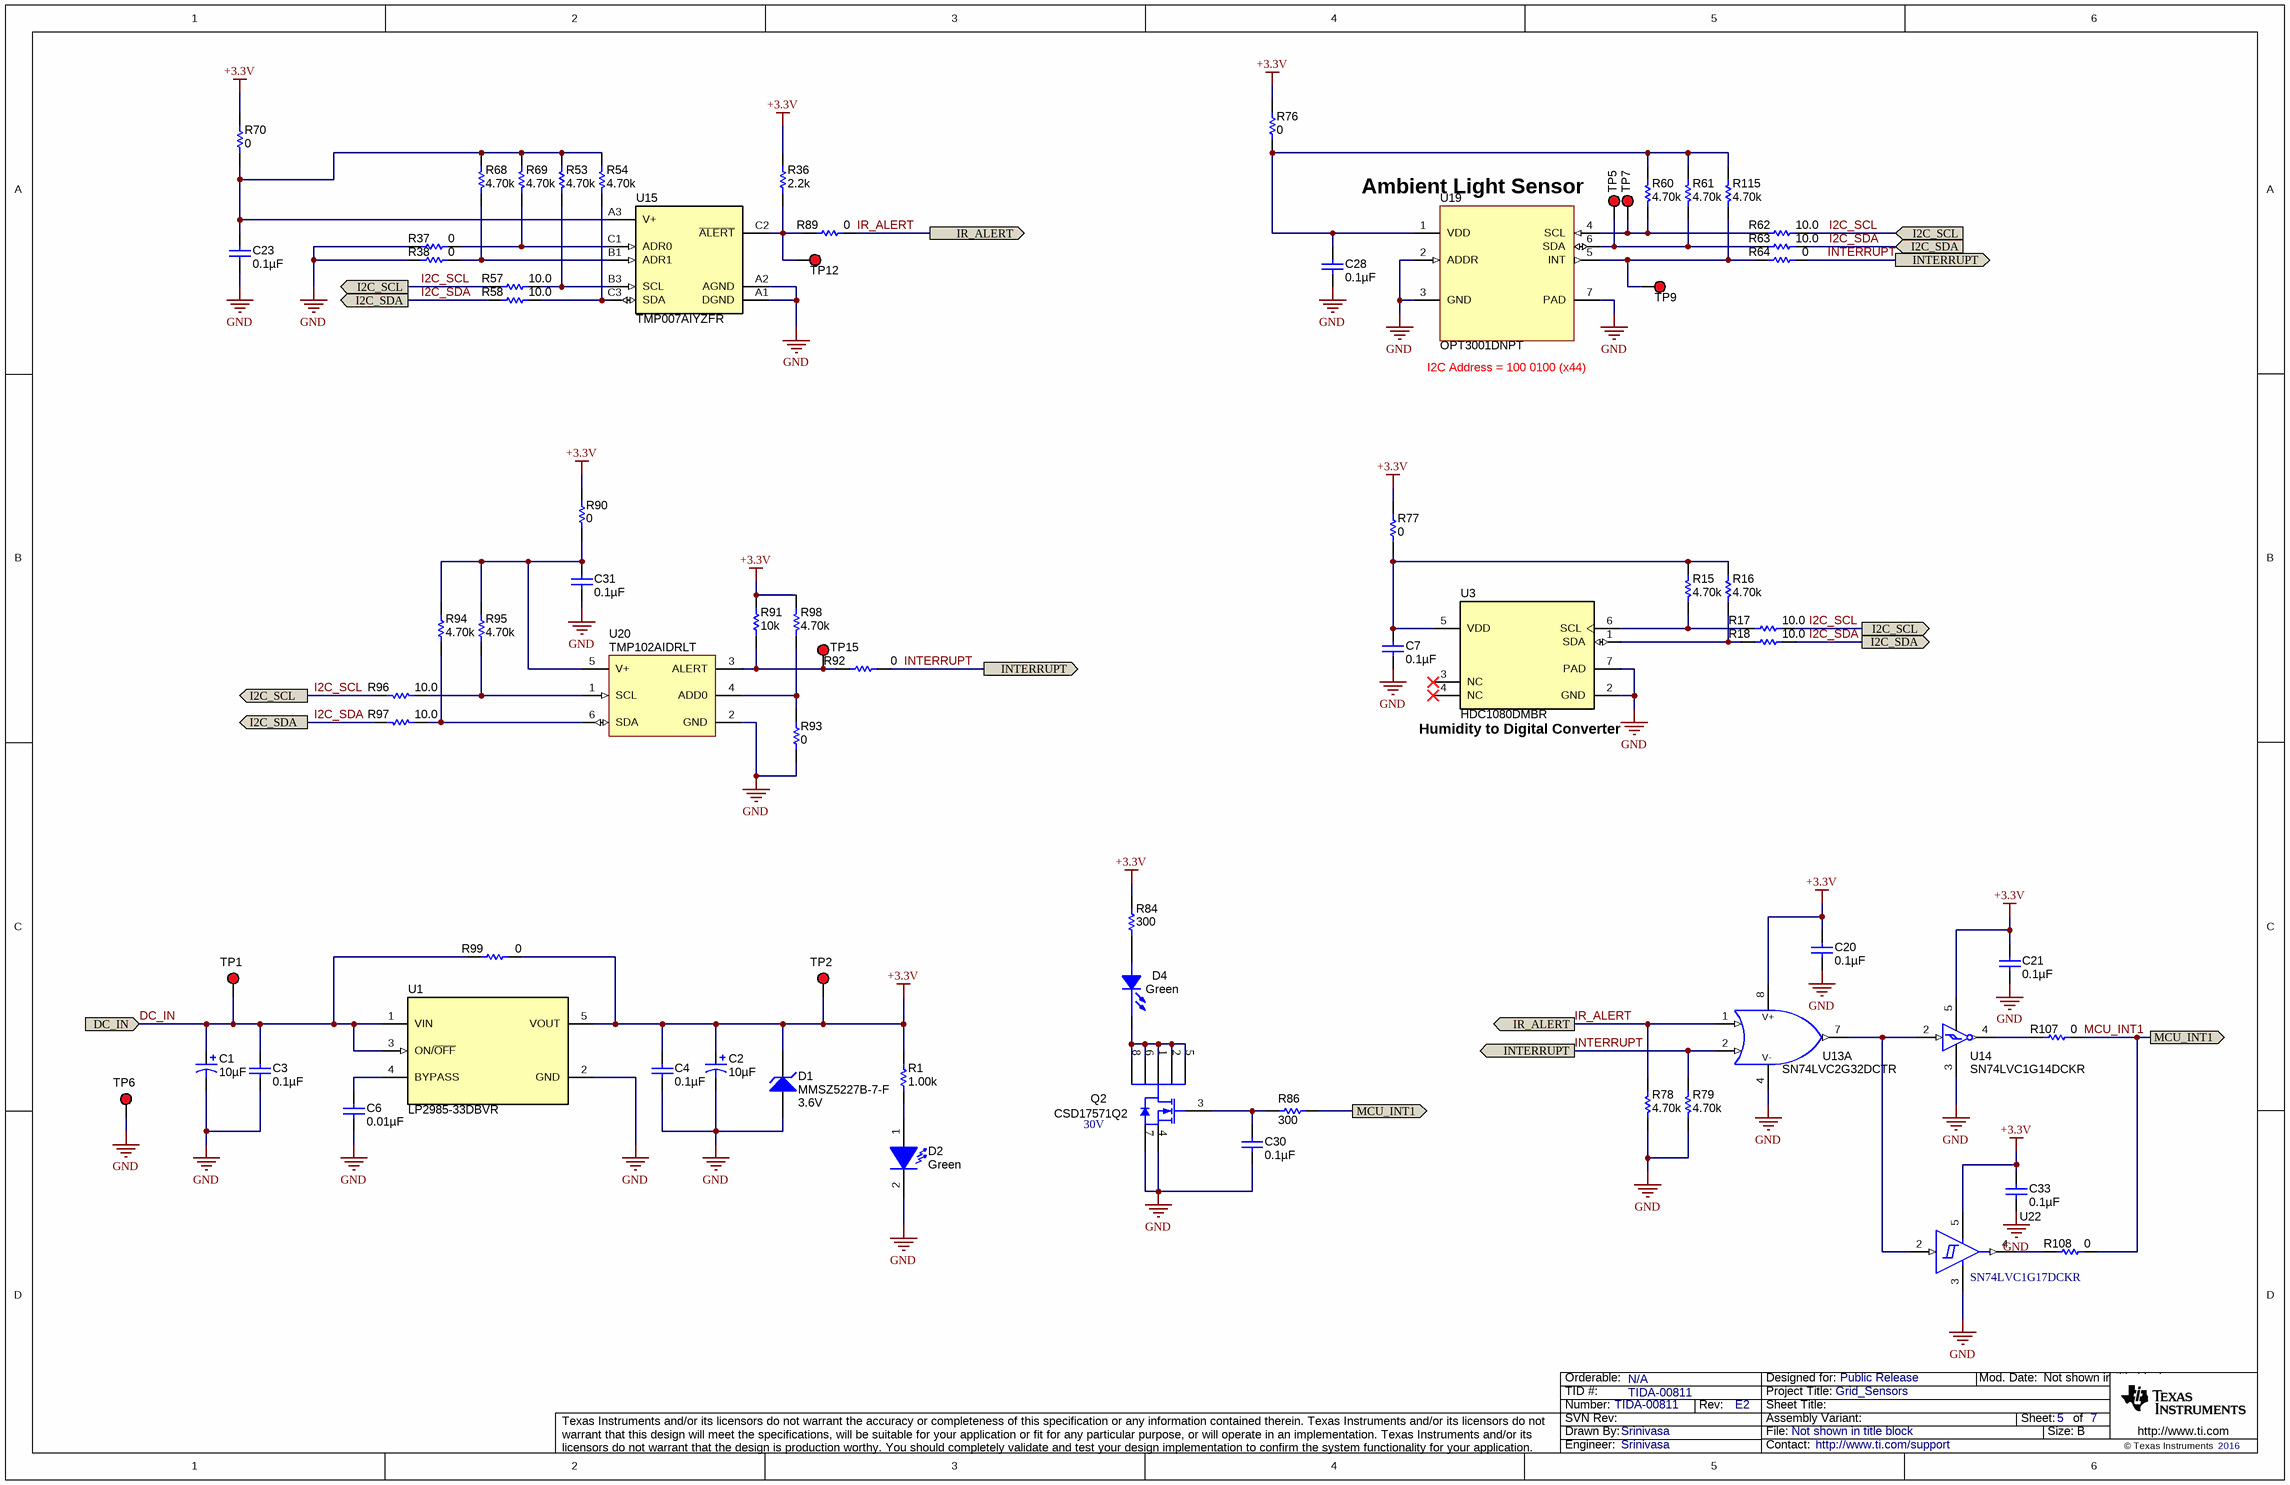
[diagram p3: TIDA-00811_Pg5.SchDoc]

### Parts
C1  ValueDisplayed: 10µF  [6032-28]  (hidden comment: 293D106X9025C2TE3)
C2  ValueDisplayed: 10µF  [6032-28]  (hidden comment: 293D106X9025C2TE3)
C3  ValueDisplayed: 0.1µF  [0603]  (hidden comment: 06033C104JAT2A)
C4  ValueDisplayed: 0.1µF  [0603]  (hidden comment: 06033C104JAT2A)
C6  ValueDisplayed: 0.01µF  [0603]  (hidden comment: C1608C0G1E103J080AA)
C7  ValueDisplayed: 0.1µF  [0603]  (hidden comment: 06033C104JAT2A)
C20  ValueDisplayed: 0.1µF  [0603]  (hidden comment: 06033C104JAT2A)
C21  ValueDisplayed: 0.1µF  [0603]  (hidden comment: 06033C104JAT2A)
C23  ValueDisplayed: 0.1µF  [0603]  (hidden comment: 06033C104JAT2A)
C28  ValueDisplayed: 0.1µF  [0603]  (hidden comment: 06033C104JAT2A)
C30  ValueDisplayed: 0.1µF  [0603]  (hidden comment: 06033C104JAT2A)
C31  ValueDisplayed: 0.1µF  [0603]  (hidden comment: 06033C104JAT2A)
C33  ValueDisplayed: 0.1µF  [0603]  (hidden comment: 06033C104JAT2A)
D1  MMSZ5227B-7-F  value 3.6V  [SOD-123]
D2  value Green  [LG L29K_GREEN]  (hidden comment: LG L29K-G2J1-24-Z)
D4  value Green  [LED0603AA]  (hidden comment: LED_LG L29K-G2J1-24-Z)
Q2  CSD17571Q2  value 30V  [SON_CSD17571Q2]
R1  ValueDisplayed: 1.00k  [0603]  (hidden comment: RC0603FR-071KL)
R15  ValueDisplayed: 4.70k  [0603]  (hidden comment: RC0603FR-074K7L)
R16  ValueDisplayed: 4.70k  [0603]  (hidden comment: RC0603FR-074K7L)
R17  ValueDisplayed: 10.0  [0603]  (hidden comment: CRCW060310R0FKEA)
R18  ValueDisplayed: 10.0  [0603]  (hidden comment: CRCW060310R0FKEA)
R36  ValueDisplayed: 2.2k  [0603]  (hidden comment: RC0603JR-072K2L)
R37  ValueDisplayed: 0  [0603]  (hidden comment: RC0603JR-070RL)
R38  ValueDisplayed: 0  [0603]  (hidden comment: RC0603JR-070RL)
R53  ValueDisplayed: 4.70k  [0603]  (hidden comment: RC0603FR-074K7L)
R54  ValueDisplayed: 4.70k  [0603]  (hidden comment: RC0603FR-074K7L)
R57  ValueDisplayed: 10.0  [0603]  (hidden comment: CRCW060310R0FKEA)
R58  ValueDisplayed: 10.0  [0603]  (hidden comment: CRCW060310R0FKEA)
R60  ValueDisplayed: 4.70k  [0603]  (hidden comment: RC0603FR-074K7L)
R61  ValueDisplayed: 4.70k  [0603]  (hidden comment: RC0603FR-074K7L)
R62  ValueDisplayed: 10.0  [0603]  (hidden comment: CRCW060310R0FKEA)
R63  ValueDisplayed: 10.0  [0603]  (hidden comment: CRCW060310R0FKEA)
R64  ValueDisplayed: 0  [0603]  (hidden comment: RC0603JR-070RL)
R68  ValueDisplayed: 4.70k  [0603]  (hidden comment: RC0603FR-074K7L)
R69  ValueDisplayed: 4.70k  [0603]  (hidden comment: RC0603FR-074K7L)
R70  ValueDisplayed: 0  [0603]  (hidden comment: RC0603JR-070RL)
R76  ValueDisplayed: 0  [0603]  (hidden comment: RC0603JR-070RL)
R77  ValueDisplayed: 0  [0603]  (hidden comment: RC0603JR-070RL)
R78  ValueDisplayed: 4.70k  [0603]  (hidden comment: RC0603FR-074K7L)
R79  ValueDisplayed: 4.70k  [0603]  (hidden comment: RC0603FR-074K7L)
R84  value 300  [0603]  (hidden comment: CRCW0603300RJNEA)
R86  value 300  [0603]  (hidden comment: CRCW0603300RJNEA)
R89  ValueDisplayed: 0  [0603]  (hidden comment: RC0603JR-070RL)
R90  ValueDisplayed: 0  [0603]  (hidden comment: RC0603JR-070RL)
R91  ValueDisplayed: 10k  [0603]  (hidden comment: CRCW060310K0JNEA)
R92  ValueDisplayed: 0  [0603]  (hidden comment: RC0603JR-070RL)
R93  ValueDisplayed: 0  [0603]  (hidden comment: RC0603JR-070RL)
R94  ValueDisplayed: 4.70k  [0603]  (hidden comment: RC0603FR-074K7L)
R95  ValueDisplayed: 4.70k  [0603]  (hidden comment: RC0603FR-074K7L)
R96  ValueDisplayed: 10.0  [0603]  (hidden comment: CRCW060310R0FKEA)
R97  ValueDisplayed: 10.0  [0603]  (hidden comment: CRCW060310R0FKEA)
R98  ValueDisplayed: 4.70k  [0603]  (hidden comment: RC0603FR-074K7L)
R99  ValueDisplayed: 0  [0805_HV]  (hidden comment: CRCW08050000Z0EA)
R107  ValueDisplayed: 0  [0603]  (hidden comment: RC0603JR-070RL)
R108  ValueDisplayed: 0  [0603]  (hidden comment: RC0603JR-070RL)
R115  ValueDisplayed: 4.70k  [0603]  (hidden comment: RC0603FR-074K7L)
TP1  5000  [Keystone5000]  (value not drawn)
TP2  5000  [Keystone5000]  (value not drawn)
TP5  5000  [Keystone5000]  (value not drawn)
TP6  5000  [Keystone5000]  (value not drawn)
TP7  5000  [Keystone5000]  (value not drawn)
TP9  5000  [Keystone5000]  (value not drawn)
TP12  5000  [Keystone5000]  (value not drawn)
TP15  5000  [Keystone5000]  (value not drawn)
U1  LP2985-33DBVR  [DBV0005A_N]
U3  HDC1080DMBR  [DMB0006A]
U13  SN74LVC2G32DCTR  [DCT0008A_N]  (part A of 2)
U14  SN74LVC1G14DCKR  [DCK0005A_N]
U15  TMP007AIYZFR  [YZF0008AEAE]
U19  OPT3001DNPT  [DNP0006A]
U20  TMP102AIDRLT  [DRL0006A_N]
U22  SN74LVC1G17DCKR  [DCK0005A_N]

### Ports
DC_IN (in), I2C_SCL (in), I2C_SCL (out), I2C_SDA (in), I2C_SDA (out), INTERRUPT (out), IR_ALERT (out), MCU_INT1 (out)

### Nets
+3.3V: C2.1(+) C4.1 C20.2 C21.2 C33.2 D1.1(K) R1.2 R36.2 R70.2 R76.2 R77.2 R84.2 R90.2 R91.2 R98.2 R99.2 TP2.1 U1.5(VOUT) U13.8(VCC) U14.5(VCC) U22.5(VCC)
GND: C1.2(-) C2.2(-) C3.2 C4.2 C6.2 C7.1 C20.1 C21.1 C23.1 C28.1 C30.2 C31.1 C33.1 D1.2(A) D2.2(K) Q2.4(S) Q2.7(S) R37.1 R38.1 R78.2 R79.2 R93.2 TP6.1 U1.2(GND) U3.2(GND) U3.7(PAD) U13.4(GND) U14.3(GND) U15.A1(DGND) U15.A2(AGND) U19.2(ADDR) U19.3(GND) U19.7(PAD) U20.2(GND) U22.3(GND)
DC_IN: C1.1(+) C3.1 R99.1 TP1.1 U1.1(VIN) U1.3(ON/~{OFF}) ; port DC_IN
I2C_SCL: R17.2 R57.1 R62.2 R96.2 ; port I2C_SCL
I2C_SDA: R18.2 R58.1 R63.2 R97.2 ; port I2C_SDA
INTERRUPT: R64.2 R79.1 R92.2 U13.2(1B) ; port INTERRUPT
IR_ALERT: R78.1 R89.2 U13.1(1A) ; port IR_ALERT
MCU_INT1: R86.1 R107.2 R108.2 ; port MCU_INT1
NetC6_1: C6.1 U1.4(BYPASS)
NetC7_2: C7.2 R15.2 R16.2 R77.1 U3.5(VDD)
NetC23_2: C23.2 R53.2 R54.2 R68.2 R69.2 R70.1 U15.A3(V+)
NetC28_2: C28.2 R60.2 R61.2 R76.1 R115.2 U19.1(VDD)
NetC30_1: C30.1 Q2.3(G) R86.2
NetC31_2: C31.2 R90.1 R94.2 R95.2 U20.5(V+)
NetD2_1: D2.1(A) R1.1
NetD4_1: D4.1(C) Q2.1(D) Q2.2(D) Q2.5(D) Q2.6(D) Q2.8(D)
NetD4_2: D4.2(A) R84.1
NetR15_1: R15.1 R17.1 U3.6(SCL)
NetR16_1: R16.1 R18.1 U3.1(SDA)
NetR36_1: R36.1 R89.1 TP12.1 U15.C2(~{ALERT})
NetR37_2: R37.2 R69.1 U15.C1(ADR0)
NetR38_2: R38.2 R68.1 U15.B1(ADR1)
NetR53_1: R53.1 R57.2 U15.B3(SCL)
NetR54_1: R54.1 R58.2 U15.C3(SDA)
NetR60_1: R60.1 R62.1 TP7.1 U19.4(SCL)
NetR61_1: R61.1 R63.1 TP5.1 U19.6(SDA)
NetR64_1: R64.1 R115.1 TP9.1 U19.5(INT)
NetR91_1: R91.1 R92.1 TP15.1 U20.3(ALERT)
NetR93_1: R93.1 R98.1 U20.4(ADD0)
NetR94_1: R94.1 R97.1 U20.6(SDA)
NetR95_1: R95.1 R96.1 U20.1(SCL)
NetR107_1: R107.1 U14.4(Y)
NetR108_1: R108.1 U22.4(Y)
NetU13_7: U13.7(1Y) U14.2(A) U22.2(A)

Not connected (* = marked no-connect by the designer): U3 3(NC)* 4(NC)*

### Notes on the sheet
- Ambient Light Sensor
- I2C Address = 100 0100 (x44)
- (near U3) Humidity to Digital Converter

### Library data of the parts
C1 C2 = 293D106X9025C2TE3: as C37 on sheet TIDA-00811_Pg4
C3 C4 C7 C20 C21 C23 C28 C31 C33 = 06033C104JAT2A: as C5 on sheet TIDA-00811_Pg4
C6 = C1608C0G1E103J: CAP, CERM, 0.01 µF, 25 V, +/- 5%, C0G/NP0, 0603; Manufacturer: TDK; Polarized: N; CompType: Capacitor; Value: 0.01uF; U/M: EA; Cap_F: 0.00000001; Tolerance_%: 5; Value1: Unknown; VDC_V: 25; Value2: 25V; TaMin_C: -55; TaMax_C: 125; AEC Category: Q200
C30 = 06033C104JAT2A: as C16 on sheet TIDA-00811_Pg4
D1 = MMSZ5227B-7-F: Diode, Zener, 3.6 V, 500 mW, SOD-123; Manufacturer: Diodes Inc.; SymbolCreator: a0412235; U/M: EA; Power_W: 0.5; Vz_V: 3.6; Value1: 0.5W; RJA_CperW: 350; AEC Category: Q101
D2 = LG L29K-G2J1-24-Z: LED, Green, SMD; Manufacturer: OSRAM; Vf_V: 1.7; Value2: 1.7V; Io_A: 0.002; Tjmax_C: 110; Value1: W; U/M: EA
D4 = LED_LG L29K-G2J1-24-Z: LED SmartLED Green 570NM; Manufacturer: OSRAM; SymbolCreator: x0120606
Q2 = CSD17571Q2: MOSFET, N-CH, 30V, 22A, SON 2X2 MM; Manufacturer: TEXAS INSTRUMENTS; CompType: POWER MOSFET
R1 = RC0603FR-071KL: RES, 1.00 k, 1%, 0.1 W, 0603; Manufacturer: Yageo America; CompType: Resistor; Value: 1.00k; Res_ohm: 1000; Value_Code: 1k00; Tolerance_%: 1; Power_W: 0.1; Value2: 0.1W; VDC_V: 150; TempCo: 200 ppm/C; EIA_Code: E96; U/M: EA; AEC Category: Q200
R15 R16 R53 R54 R60 R61 R68 R69 R78 R79 R94 R95 R98 R115 = RC0603FR-074K7L: as R3 on sheet TIDA-00811_Pg4
R17 R18 R57 R58 R62 R63 R96 R97 = CRCW060310R0FKEA: as R8 on sheet TIDA-00811_Pg4
R36 = RC0603JR-072K2L: RES, 2.2 k, 5%, 0.1 W, 0603; Manufacturer: Yageo America; CompType: Resistor; Value: 2.2k; Res_ohm: 2200; Value_Code: 2k20; Tolerance_%: 5; Power_W: 0.1; Value2: 0.1W; VDC_V: 50; TempCo: 100 ppm/C; SizeArea_mm2: 1.28; SizeX_mm: 1.6; SizeY_mm: 0.8; SizeZ_mm: 1; EIA_Code: E24; U/M: EA; AEC Category: Q200
R37 R38 R64 R70 R76 R77 R89 R90 R92 R93 R107 R108 = RC0603JR-070RL: as R28 on sheet TIDA-00811_Pg4
R84 R86 = CRCW0603300RJNEA: as R104 on sheet TIDA-00811_Pg4
R91 = CRCW060310K0JNEA: RES, 10 k, 5%, 0.1 W, 0603; Manufacturer: Vishay-Dale; CompType: Resistor; Value: 10k; Res_ohm: 10000; Value_Code: 10k0; Tolerance_%: 5; Power_W: 0.1; Value2: 0.1W; VDC_V: 75; TempCo: 200 ppm/C; SizeArea_mm2: 1.28; SizeX_mm: 1.6; SizeY_mm: 0.8; SizeZ_mm: 1; EIA_Code: E24; U/M: EA; AEC Category: Q200
R99 = CRCW08050000Z0EA: RES, 0, 5%, 0.125 W, 0805; Manufacturer: Vishay-Dale; CompType: Resistor; Value: 0; Value_Code: 0000; Tolerance_%: 5; Power_W: 0.125; Value2: 0.125W; VDC_V: 150; TempCo: 200 ppm/C; SizeArea_mm2: 2.5; SizeX_mm: 2; SizeY_mm: 1.25; SizeZ_mm: 1.45; EIA_Code: E24; U/M: EA; AEC Category: Q200
TP1 TP2 TP6 TP15 = 5000: Test Point, Miniature, Red, TH; Manufacturer: Keystone; CompType: Test Point Loop; ContactFinish: Silver
TP5 TP7 TP9 TP12 = 5000: as TP13 on sheet TIDA-00811_Pg4
U1 = LP2985-33DBVR: 100-mA ULTRA-LOW DROPOUT REGULATOR WITH SHUTDOWN, DBV0005A; Alternate PartNumber: LP2985-33DBVT; Manufacturer: Texas Instruments; SymbolCreator: Altium; CompType: IC; U/M: EA
U3 = HDC1080DMBR: Low Power, High Accuracy Digital Humidity Sensor with Temperature Sensor, DMB0006A; Alternate PartNumber: HDC1080DMBT; Manufacturer: Texas Instruments; SymbolCreator: a0411947; CompType: IC; U/M: EA
U13 = SN74LVC2G32DCTR: Dual 2-Input Positive-OR Gate, DCT0008A; Manufacturer: Texas Instruments; SymbolCreator: a0411947; CompType: IC; U/M: EA
U14 = SN74LVC1G14DCKR: SINGLE SCHMITT-TRIGGER INVERTER, DCK0005A; Alternate PartNumber: SN74LVC1G14DCKT; Manufacturer: Texas Instruments; SymbolCreator: a0799628; CompType: IC; U/M: EA
U15 = TMP007AIYZFR: Infrared Thermopile Sensor with Integrated Math Engine, YZF0008AEAE; Alternate PartNumber: TMP007AIYZFT; Manufacturer: Texas Instruments; SymbolCreator: a0411947; SizeArea_mm2: 2.359296; SizeAreaWB_mm2: 6.431296; SizeX_mm: 1.536; SizeZ_mm: 0.625; CompType: IC; U/M: EA
U19 = OPT3001DNP: Ambient Light Sensor, DNP0006A; Manufacturer: Texas Instruments; SymbolCreator: a0411947; CompType: IC; U/M: EA
U20 = TMP102AIDRL: Low Power Digital Temperature Sensor With SMBus/Two-Wire Serial Interface in SOT563, DRL0006A; Alternate Manufacturer: None; Manufacturer: Texas Instruments; SymbolCreator: a0411947; CompType: IC; U/M: EA
U22 = SN74LVC1G17DCKR: SINGLE SCHMITT-TRIGGER BUFFER, DCK0005A (SOT-5); Alternate PartNumber: SN74LVC1G17DCKT; Manufacturer: Texas Instruments; SymbolCreator: a0799628; SizeArea_mm2: 4.2; SizeAreaWB_mm2: 9.3; SizeX_mm: 2.1; SizeY_mm: 2; SizeZ_mm: 1.1; CompType: IC; U/M: EA

## Sheet TIDA-00811_Pg6.SchDoc
size 431 x 279 mm; Date: Not shown in title block; ApprovedBy: Not shown in title block; CheckedBy: Not shown in title block; Author: Not shown in title block; CompanyName: Not shown in title block; DrawnBy: Srinivasa; Engineer: Not shown in title block; Organization: Not shown in title block; Address1: Not shown in title block; Address2: Not shown in title block; Address3: Not shown in title block; Address4: Not shown in title block; DocumentNumber: 1; Revision: Use project parameter SCH_Rev; SheetNumber: 6; SheetTotal: 7; PageSetup: Record=PageOptions¦CenterHorizontal=True¦CenterVertical=True¦PrintScale=1.00¦XCorrection=1.00¦YCorrection=1.00¦PrintKind=0¦BorderSize=5000000¦LeftOffset=0¦BottomOffset=0¦Orientation=2¦PaperLength=1000¦PaperWidth=1000¦Scale=100¦PaperSource=15¦PrintQuality=600¦MediaType=1¦DitherType=10¦PaperKind=Letter¦PrintScaleMode=1
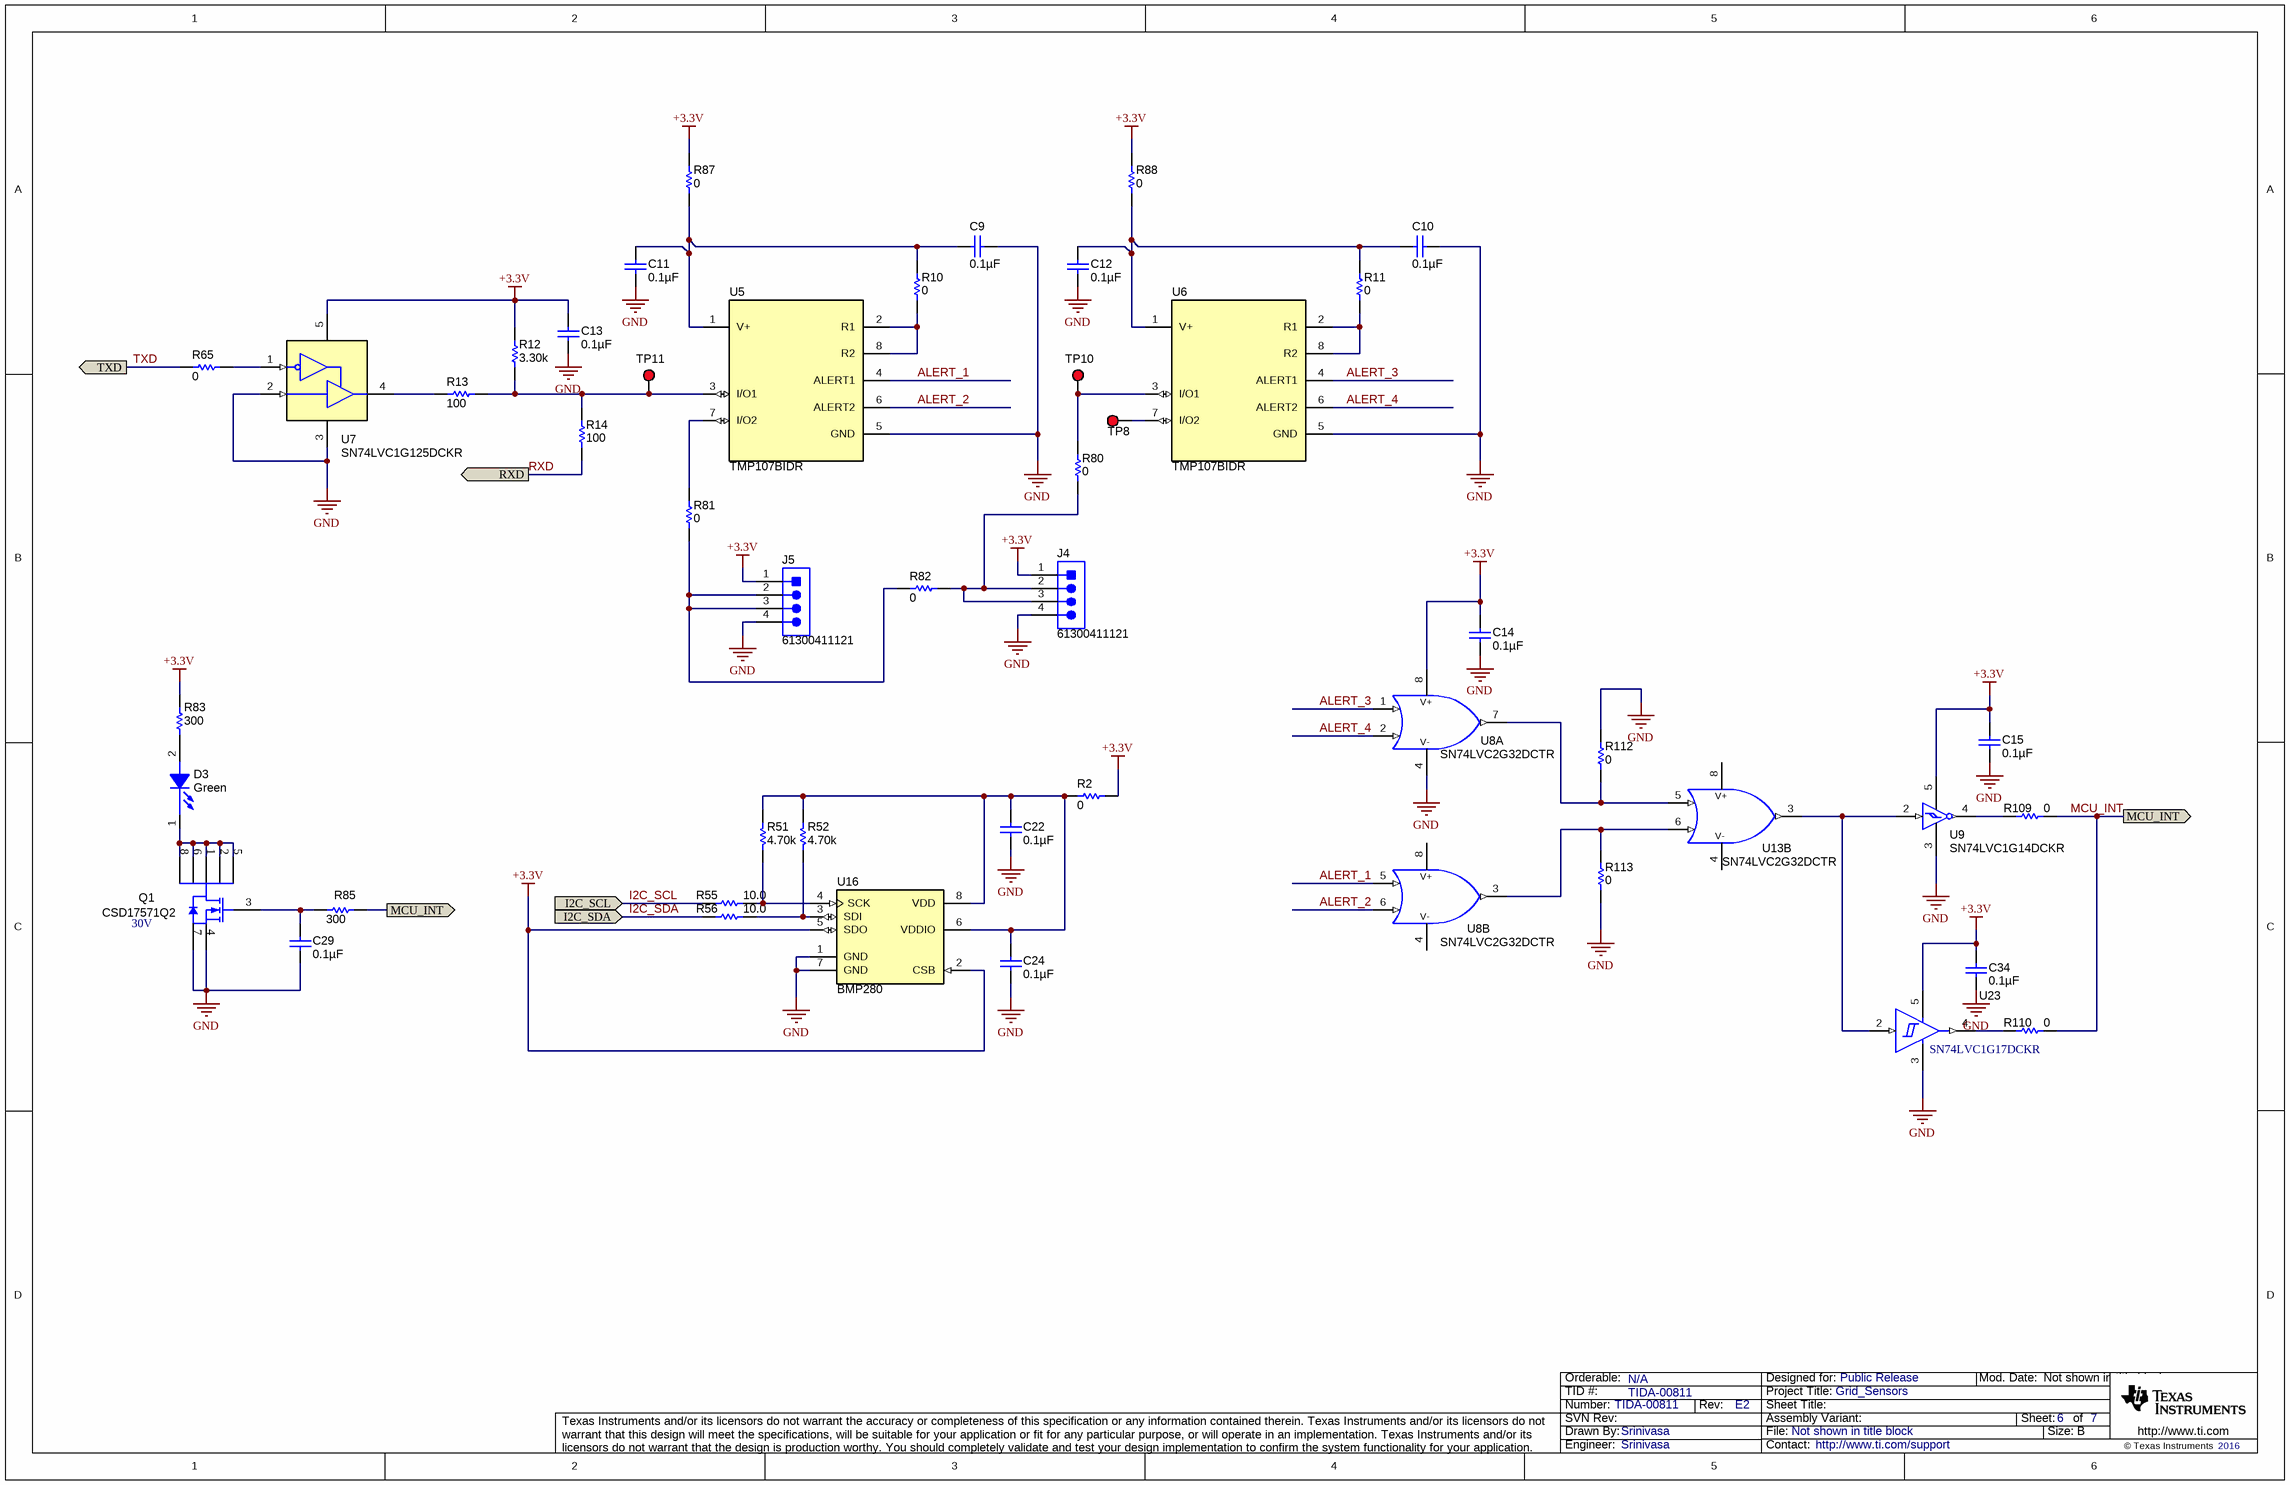
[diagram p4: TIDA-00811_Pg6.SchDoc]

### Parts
C9  ValueDisplayed: 0.1µF  [0603]  (hidden comment: 06033C104JAT2A)
C10  ValueDisplayed: 0.1µF  [0603]  (hidden comment: 06033C104JAT2A)
C11  ValueDisplayed: 0.1µF  [0603]  (hidden comment: 06033C104JAT2A)
C12  ValueDisplayed: 0.1µF  [0603]  (hidden comment: 06033C104JAT2A)
C13  ValueDisplayed: 0.1µF  [0603]  (hidden comment: 06033C104JAT2A)
C14  ValueDisplayed: 0.1µF  [0603]  (hidden comment: 06033C104JAT2A)
C15  ValueDisplayed: 0.1µF  [0603]  (hidden comment: 06033C104JAT2A)
C22  ValueDisplayed: 0.1µF  [0603]  (hidden comment: 06033C104JAT2A)
C24  ValueDisplayed: 0.1µF  [0603]  (hidden comment: 06033C104JAT2A)
C29  ValueDisplayed: 0.1µF  [0603]  (hidden comment: 06033C104JAT2A)
C34  ValueDisplayed: 0.1µF  [0603]  (hidden comment: 06033C104JAT2A)
D3  value Green  [LED0603AA]  (hidden comment: LED_LG L29K-G2J1-24-Z)
J4  61300411121  [Mill-Max_342-xx-104-00-592000]
J5  61300411121  [Mill-Max_342-xx-104-00-592000]
Q1  CSD17571Q2  value 30V  [SON_CSD17571Q2]
R2  ValueDisplayed: 0  [0603]  (hidden comment: RC0603JR-070RL)
R10  ValueDisplayed: 0  [0603]  (hidden comment: RC0603JR-070RL)
R11  ValueDisplayed: 0  [0603]  (hidden comment: RC0603JR-070RL)
R12  ValueDisplayed: 3.30k  [0603]  (hidden comment: RC0603FR-073K3L)
R13  ValueDisplayed: 100  [0603]  (hidden comment: RC0603FR-07100RL)
R14  ValueDisplayed: 100  [0603]  (hidden comment: RC0603FR-07100RL)
R51  ValueDisplayed: 4.70k  [0603]  (hidden comment: RC0603FR-074K7L)
R52  ValueDisplayed: 4.70k  [0603]  (hidden comment: RC0603FR-074K7L)
R55  ValueDisplayed: 10.0  [0603]  (hidden comment: CRCW060310R0FKEA)
R56  ValueDisplayed: 10.0  [0603]  (hidden comment: CRCW060310R0FKEA)
R65  ValueDisplayed: 0  [0603]  (hidden comment: RC0603JR-070RL)
R80  ValueDisplayed: 0  [0603]  (hidden comment: RC0603JR-070RL)
R81  ValueDisplayed: 0  [0603]  (hidden comment: RC0603JR-070RL)
R82  ValueDisplayed: 0  [0603]  (hidden comment: RC0603JR-070RL)
R83  value 300  [0603]  (hidden comment: CRCW0603300RJNEA)
R85  value 300  [0603]  (hidden comment: CRCW0603300RJNEA)
R87  ValueDisplayed: 0  [0603]  (hidden comment: RC0603JR-070RL)
R88  ValueDisplayed: 0  [0603]  (hidden comment: RC0603JR-070RL)
R109  ValueDisplayed: 0  [0603]  (hidden comment: RC0603JR-070RL)
R110  ValueDisplayed: 0  [0603]  (hidden comment: RC0603JR-070RL)
R112  ValueDisplayed: 0  [0603]  (hidden comment: RC0603JR-070RL)
R113  ValueDisplayed: 0  [0603]  (hidden comment: RC0603JR-070RL)
TP8  5000  [Keystone5000]  (value not drawn)
TP10  5000  [Keystone5000]  (value not drawn)
TP11  5000  [Keystone5000]  (value not drawn)
U5  TMP107BIDR  [D0008A_N]
U6  TMP107BIDR  [D0008A_N]
U7  SN74LVC1G125DCKR  [DCK0005A_N]
U8  SN74LVC2G32DCTR  [DCT0008A_N]  (parts A,B of 2)
U9  SN74LVC1G14DCKR  [DCK0005A_N]
U13  SN74LVC2G32DCTR  [DCT0008A_N]  (part B of 2)
U16  BMP280  [LGA8-2X2_5MM_0_65]
U23  SN74LVC1G17DCKR  [DCK0005A_N]

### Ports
I2C_SCL (in), I2C_SDA (in), MCU_INT (out), RXD (out), TXD (out)

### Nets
+3.3V: C13.2 C14.2 C15.2 C34.2 J4.1 J5.1 R2.1 R12.2 R83.2 R87.1 R88.1 U7.5(VCC) U8.8(VCC) U9.5(VCC) U13.8(VCC) U16.2(CSB) U16.5(SDO) U23.5(VCC)
GND: C9.2 C10.2 C11.1 C12.1 C13.1 C14.1 C15.1 C22.1 C24.1 C29.2 C34.1 J4.4 J5.4 Q1.4(S) Q1.7(S) R112.2 R113.1 U5.5(GND) U6.5(GND) U7.2(A) U7.3(GND) U8.4(GND) U9.3(GND) U13.4(GND) U16.1(GND) U16.7(GND) U23.3(GND)
ALERT_1: U5.4(ALERT1) U8.5(2A)
ALERT_2: U5.6(ALERT2) U8.6(2B)
ALERT_3: U6.4(ALERT1) U8.1(1A)
ALERT_4: U6.6(ALERT2) U8.2(1B)
I2C_SCL: R55.1 ; port I2C_SCL
I2C_SDA: R56.1 ; port I2C_SDA
MCU_INT: R85.1 R109.2 R110.2 ; port MCU_INT
RXD: R14.1 ; port RXD
TXD: R65.2 ; port TXD
NetC9_1: C9.1 C11.2 R10.1 R87.2 U5.1(V+)
NetC10_1: C10.1 C12.2 R11.1 R88.2 U6.1(V+)
NetC22_2: C22.2 C24.2 R2.2 R51.2 R52.2 U16.6(VDDIO) U16.8(VDD)
NetC29_1: C29.1 Q1.3(G) R85.2
NetD3_1: D3.1(C) Q1.1(D) Q1.2(D) Q1.5(D) Q1.6(D) Q1.8(D)
NetD3_2: D3.2(A) R83.1
NetJ4_2: J4.2 J4.3 R80.1 R82.2
NetJ5_2: J5.2 J5.3 R81.2 R82.1
NetR10_2: R10.2 U5.2(R1) U5.8(R2)
NetR11_2: R11.2 U6.2(R1) U6.8(R2)
NetR12_1: R12.1 R13.2 R14.2 TP11.1 U5.3(I/O1)
NetR13_1: R13.1 U7.4(Y)
NetR51_1: R51.1 R55.2 U16.4(SCK)
NetR52_1: R52.1 R56.2 U16.3(SDI)
NetR65_1: R65.1 U7.1(~{OE})
NetR80_2: R80.2 TP10.1 U6.3(I/O1)
NetR81_1: R81.1 U5.7(I/O2)
NetR109_1: R109.1 U9.4(Y)
NetR110_1: R110.1 U23.4(Y)
NetR112_1: R112.1 U8.7(1Y) U13.5(2A)
NetR113_2: R113.2 U8.3(2Y) U13.6(2B)
NetTP8_1: TP8.1 U6.7(I/O2)
NetU9_2: U9.2(A) U13.3(2Y) U23.2(A)

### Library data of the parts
C9-C15 C22 C24 C34 = 06033C104JAT2A: as C5 on sheet TIDA-00811_Pg4
C29 = 06033C104JAT2A: as C16 on sheet TIDA-00811_Pg4
D3 = LED_LG L29K-G2J1-24-Z: as D4 on sheet TIDA-00811_Pg5
J4 J5 = 342-10-104-00-592000: Header, 2.54mm, 4x1, Gold, TH; Manufacturer: Mill-Max; SymbolCreator: a0412235; Pitch_mm: 2.54; Gender: Male; Shrouded: N; Row_Count: 1
Q1 = CSD17571Q2: as Q2 on sheet TIDA-00811_Pg5
R2 R10 R11 R65 R80-R82 R87 R88 R109 R110 R112 R113 = RC0603JR-070RL: as R28 on sheet TIDA-00811_Pg4
R12 = RC0603FR-073K3L: RES, 3.30 k, 1%, 0.1 W, 0603; Manufacturer: Yageo America; CompType: Resistor; Value: 3.30k; Res_ohm: 3300; Value_Code: 3k30; Tolerance_%: 1; Power_W: 0.1; Value2: 0.1W; VDC_V: 150; TempCo: 200 ppm/C; U/M: EA; AEC Category: Q200
R13 R14 = RC0603FR-07100RL: RES, 100, 1%, 0.1 W, 0603; Manufacturer: Yageo America; CompType: Resistor; Value: 100; Value_Code: 100R; Tolerance_%: 1; Power_W: 0.1; Value2: 0.1W; VDC_V: 150; TempCo: 200 ppm/C; EIA_Code: E96; U/M: EA; AEC Category: Q200
R51 R52 = RC0603FR-074K7L: as R3 on sheet TIDA-00811_Pg4
R55 R56 = CRCW060310R0FKEA: as R8 on sheet TIDA-00811_Pg4
R83 R85 = CRCW0603300RJNEA: as R104 on sheet TIDA-00811_Pg4
TP8 TP10 TP11 = 5000: as TP1 on sheet TIDA-00811_Pg5
U5 U6 = TMP107BIDR: TMP107B, D0008A; Manufacturer: Texas Instruments; SymbolCreator: Altium; CompType: IC; U/M: EA
U7 = SN74LVC1G125DCKR: Single Bus Buffer Gate With 3-State Output, DCK0005A; Alternate PartNumber: SN74LVC1G125DCKT; Manufacturer: Texas Instruments; SymbolCreator: Altium; CompType: IC; U/M: EA
U8 U13 = SN74LVC2G32DCTR: as U13 on sheet TIDA-00811_Pg5
U9 = SN74LVC1G14DCKR: as U14 on sheet TIDA-00811_Pg5
U16 = BMP280: Digital Pressure Sensor, LGA8-2X2_5MM_0_65; Manufacturer: Bosch Solar Energy; SymbolCreator: Altium
U23 = SN74LVC1G17DCKR: as U22 on sheet TIDA-00811_Pg5

## Sheet TIDA-00811_Pg7_EVM_Hardware.SchDoc
size 431 x 279 mm; Date: Not shown in title block; ApprovedBy: Not shown in title block; CheckedBy: Not shown in title block; Author: Not shown in title block; CompanyName: Not shown in title block; DrawnBy: Srinivasa; Engineer: Not shown in title block; Organization: Not shown in title block; Address1: Not shown in title block; Address2: Not shown in title block; Address3: Not shown in title block; Address4: Not shown in title block; DocumentNumber: 1; Revision: Use project parameter SCH_Rev; SheetNumber: 7; SheetTotal: 7; PageSetup: Record=PageOptions¦CenterHorizontal=True¦CenterVertical=True¦PrintScale=1.00¦XCorrection=1.00¦YCorrection=1.00¦PrintKind=0¦BorderSize=5000000¦LeftOffset=0¦BottomOffset=0¦Orientation=2¦PaperLength=1000¦PaperWidth=1000¦Scale=100¦PaperSource=15¦PrintQuality=600¦MediaType=1¦DitherType=10¦PaperKind=Letter¦PrintScaleMode=1
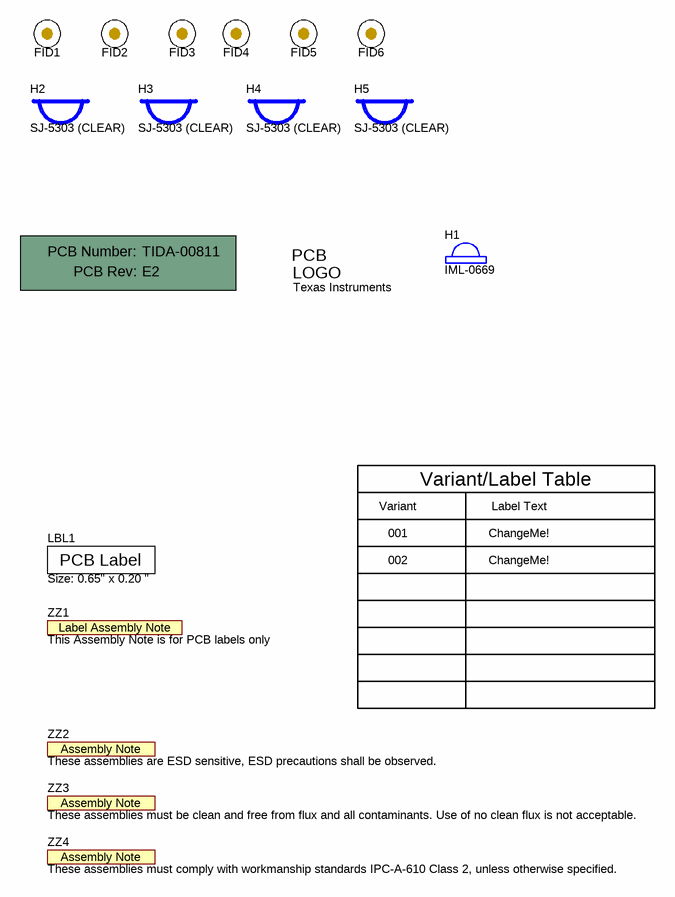
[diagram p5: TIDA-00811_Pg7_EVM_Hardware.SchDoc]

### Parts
!PCB1  Printed Circuit Board  (value not drawn)  (mechanical)
FID1  Fiducial  [Fiducial10-20]  (value not drawn)
FID2  Fiducial  [Fiducial10-20]  (value not drawn)
FID3  Fiducial  [Fiducial10-20]  (value not drawn)
FID4  Fiducial  [Fiducial10-20]  (value not drawn)
FID5  Fiducial  [Fiducial10-20]  (value not drawn)
FID6  Fiducial  [Fiducial10-20]  (value not drawn)
H1  IML-0669  [Murata_IML-0669]
H2  SJ-5303 (CLEAR)  [Bumpon_SJ5003Transparent]
H3  SJ-5303 (CLEAR)  [Bumpon_SJ5003Transparent]
H4  SJ-5303 (CLEAR)  [Bumpon_SJ5003Transparent]
H5  SJ-5303 (CLEAR)  [Bumpon_SJ5003Transparent]
LBL1  Size: 0.65" x 0.20 "  [Label_650x200]
Logo1  Texas Instruments  [TI_Stacked_Overlay_Small]  (no BOM)
ZZ1  This Assembly Note is for PCB labels only  [AssemblyNoteLabel]  (no BOM)
ZZ2  These assemblies are ESD sensitive, ESD precautions shall be observed.  [AssemblyNote]  (no BOM)
ZZ3  These assemblies must be clean and free from flux and all contaminants. Use of no clean flux is not acceptable.  [AssemblyNote]  (no BOM)
ZZ4  These assemblies must comply with workmanship standards IPC-A-610 Class 2, unless otherwise specified.  [AssemblyNote]  (no BOM)

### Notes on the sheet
- Variant
- Variant/Label Table
- Label Text
- 001
- 002
- ChangeMe!

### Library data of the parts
!PCB1 = PCB: Manufacturer: Any; PartNumber: TIDA-00811; SymbolCreator: a0412235
FID1-FID6 = Fiducial: Fiducial mark.  There is nothing to buy or mount.; SymbolCreator: codlsc
H1 = IML-0669: Lens, Ceiling Mount, TH; Manufacturer: MuRata; SymbolCreator: Altium
H2-H5 = SJ-5303 (CLEAR): Bumpon, Hemisphere, 0.44 X 0.20, Clear; Manufacturer: 3M; SymbolCreator: a0412235
LBL1 = THT-14-423-10: Thermal Transfer Printable Labels, 0.650" W x 0.200" H - 10,000 per roll; Manufacturer: Brady; SymbolCreator: a0412235; CompType: Label
Logo1 = TI_Logo: Texas Instrument Corporate Signature; SymbolCreator: codlsc
ZZ1 = AssemblyNoteLabel: SymbolCreator: a0412235
ZZ2-ZZ4 = AssemblyNote: SymbolCreator: codlsc

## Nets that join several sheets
+3.3V: TIDA-00811_Pg4 (23 pins), TIDA-00811_Pg5 (21 pins), TIDA-00811_Pg6 (18 pins)
GND: TIDA-00811_Pg4 (30 pins), TIDA-00811_Pg5 (35 pins), TIDA-00811_Pg6 (27 pins)
DC_IN: TIDA-00811_Pg4 (J1.5), TIDA-00811_Pg5 (6 pins)
I2C_SCL: TIDA-00811_Pg4 (7 pins), TIDA-00811_Pg5 (R17.2 R57.1 R62.2 R96.2), TIDA-00811_Pg6 (R55.1)
I2C_SDA: TIDA-00811_Pg4 (7 pins), TIDA-00811_Pg5 (R18.2 R58.1 R63.2 R97.2), TIDA-00811_Pg6 (R56.1)
INTERRUPT: TIDA-00811_Pg4 (R35.2), TIDA-00811_Pg5 (R64.2 R79.1 R92.2 U13.2)
IR_ALERT: TIDA-00811_Pg4 (R59.2), TIDA-00811_Pg5 (R78.1 R89.2 U13.1)
MCU_INT: TIDA-00811_Pg4 (J2.5), TIDA-00811_Pg6 (R85.1 R109.2 R110.2)
MCU_INT1: TIDA-00811_Pg4 (J1.1), TIDA-00811_Pg5 (R86.1 R107.2 R108.2)
RXD: TIDA-00811_Pg4 (J2.1), TIDA-00811_Pg6 (R14.1)
TXD: TIDA-00811_Pg4 (J2.2), TIDA-00811_Pg6 (R65.2)

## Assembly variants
001: not fitted C29 C30 C36 FID1 FID2 FID3 FID4 FID5 FID6 R15 R16 R20 R21 R27 R30 R31 R32 R37 R42 R43 R45 R48 R49 R51 R52 R53 R54 R60 R61 R64 R68 R72 R73 R78 R79 R89 R92 R93 R94 R95 R99 R100 R103 R108 R110 R112 R113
